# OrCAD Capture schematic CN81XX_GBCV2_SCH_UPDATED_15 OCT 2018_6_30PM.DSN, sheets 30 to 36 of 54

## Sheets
30 34.V0P9_DLM & V1P2_DDR: size B; title: V0P9_DLM&V1P2_DDR
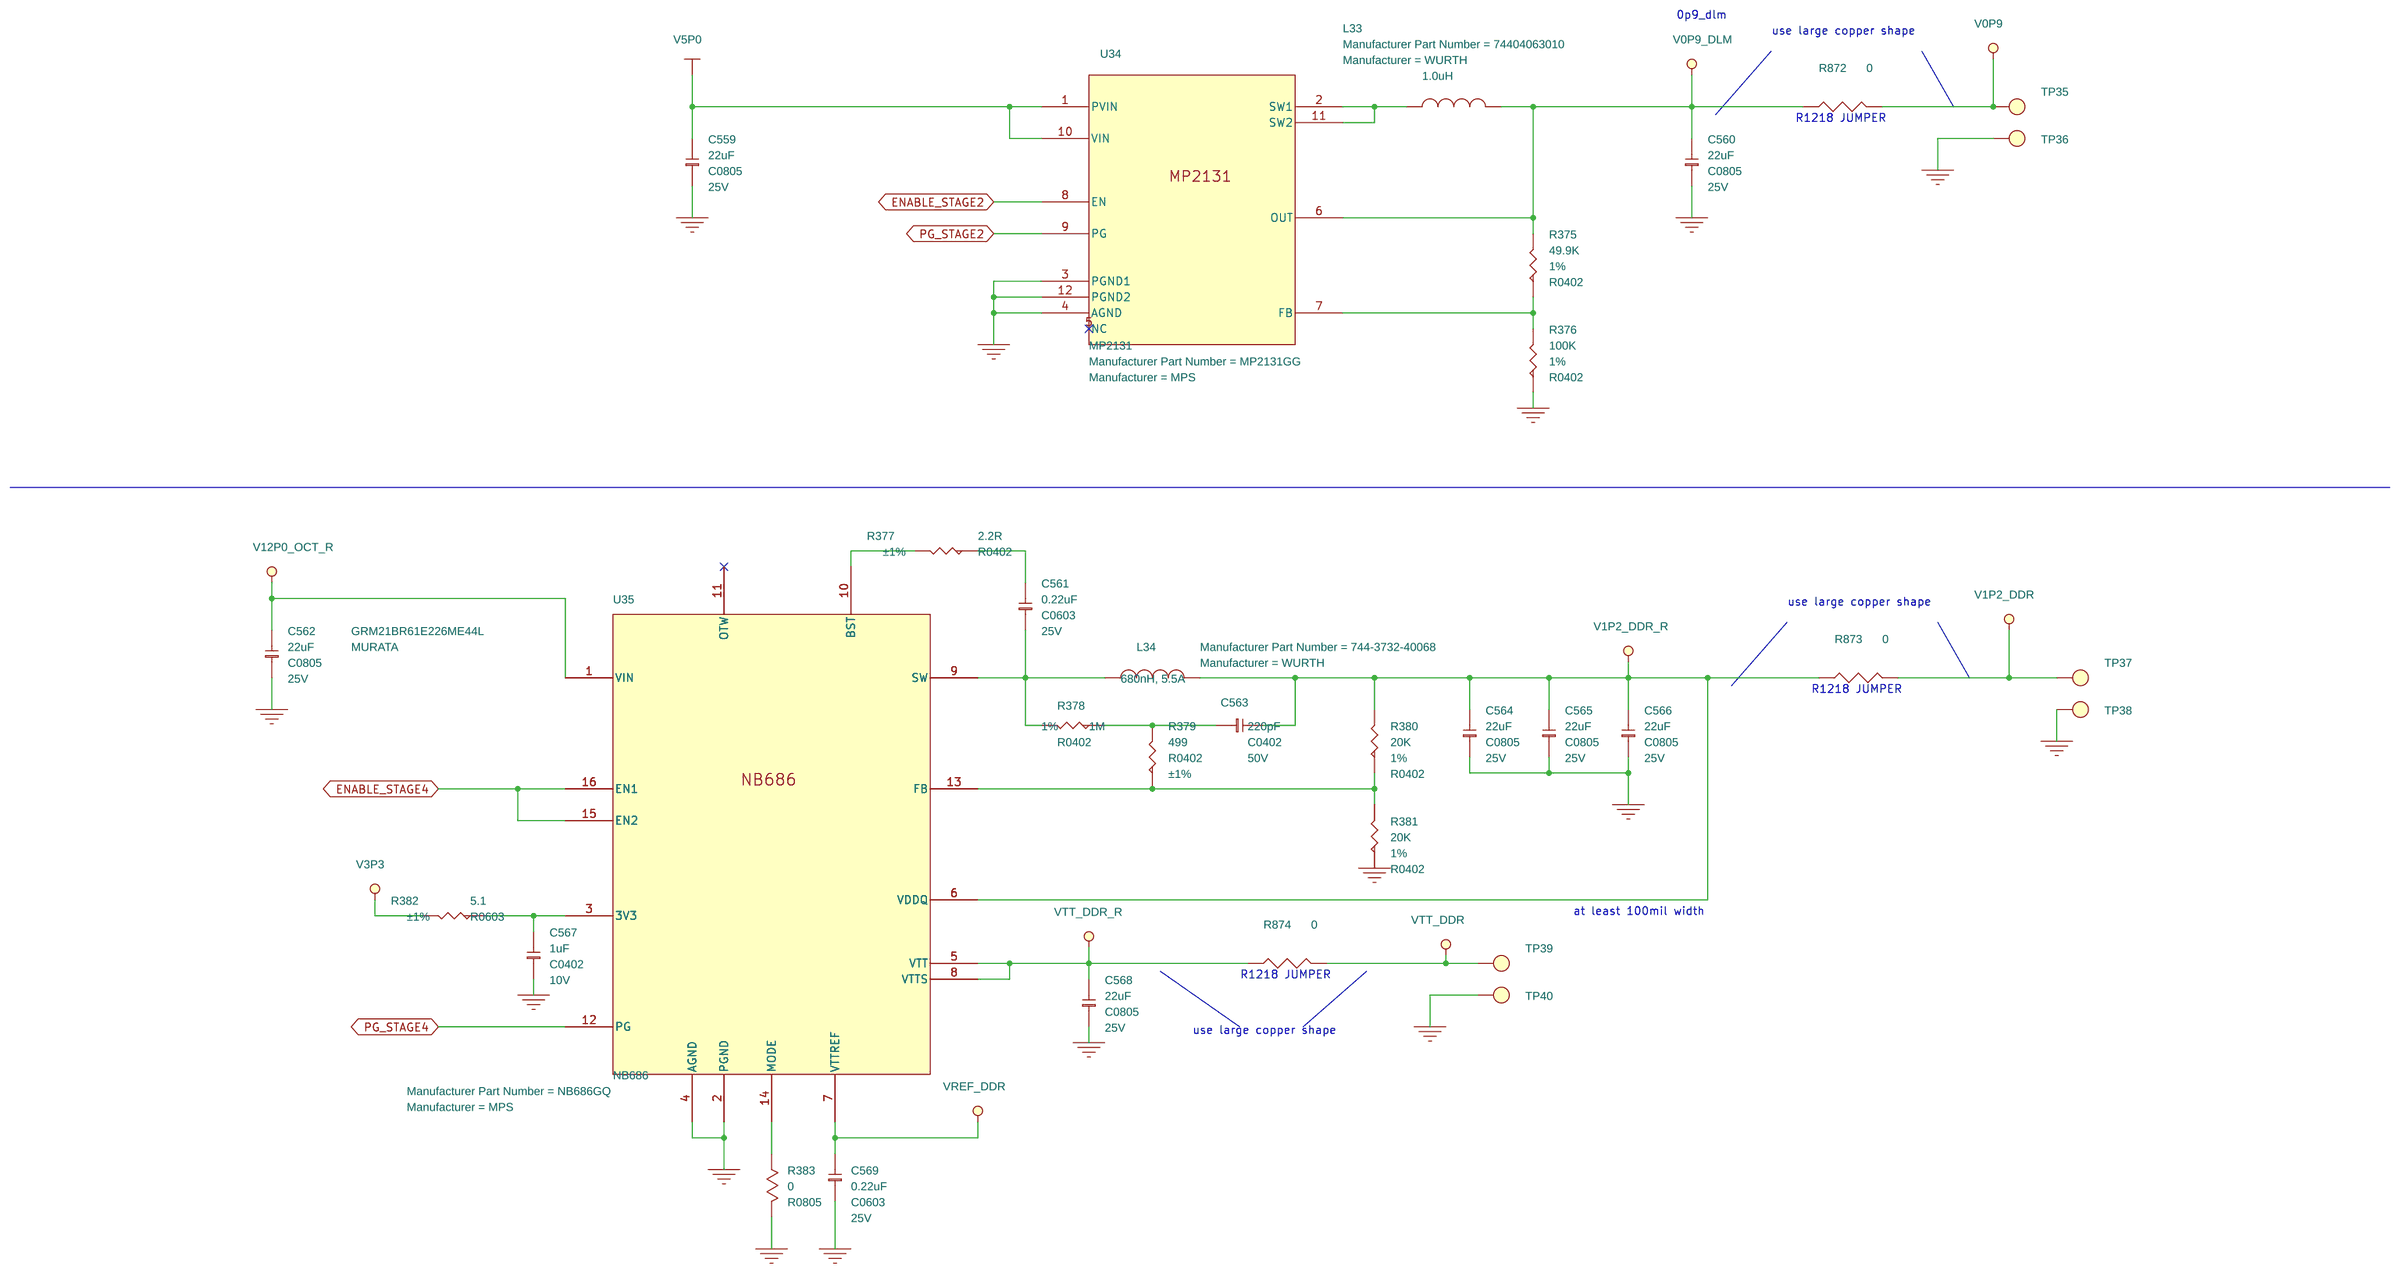
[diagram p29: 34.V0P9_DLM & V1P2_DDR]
31 35.TRXFE_PWR,V2P5,V0P9_ PLL: size B; title: V1P2,V2P5,V0P9_PLL
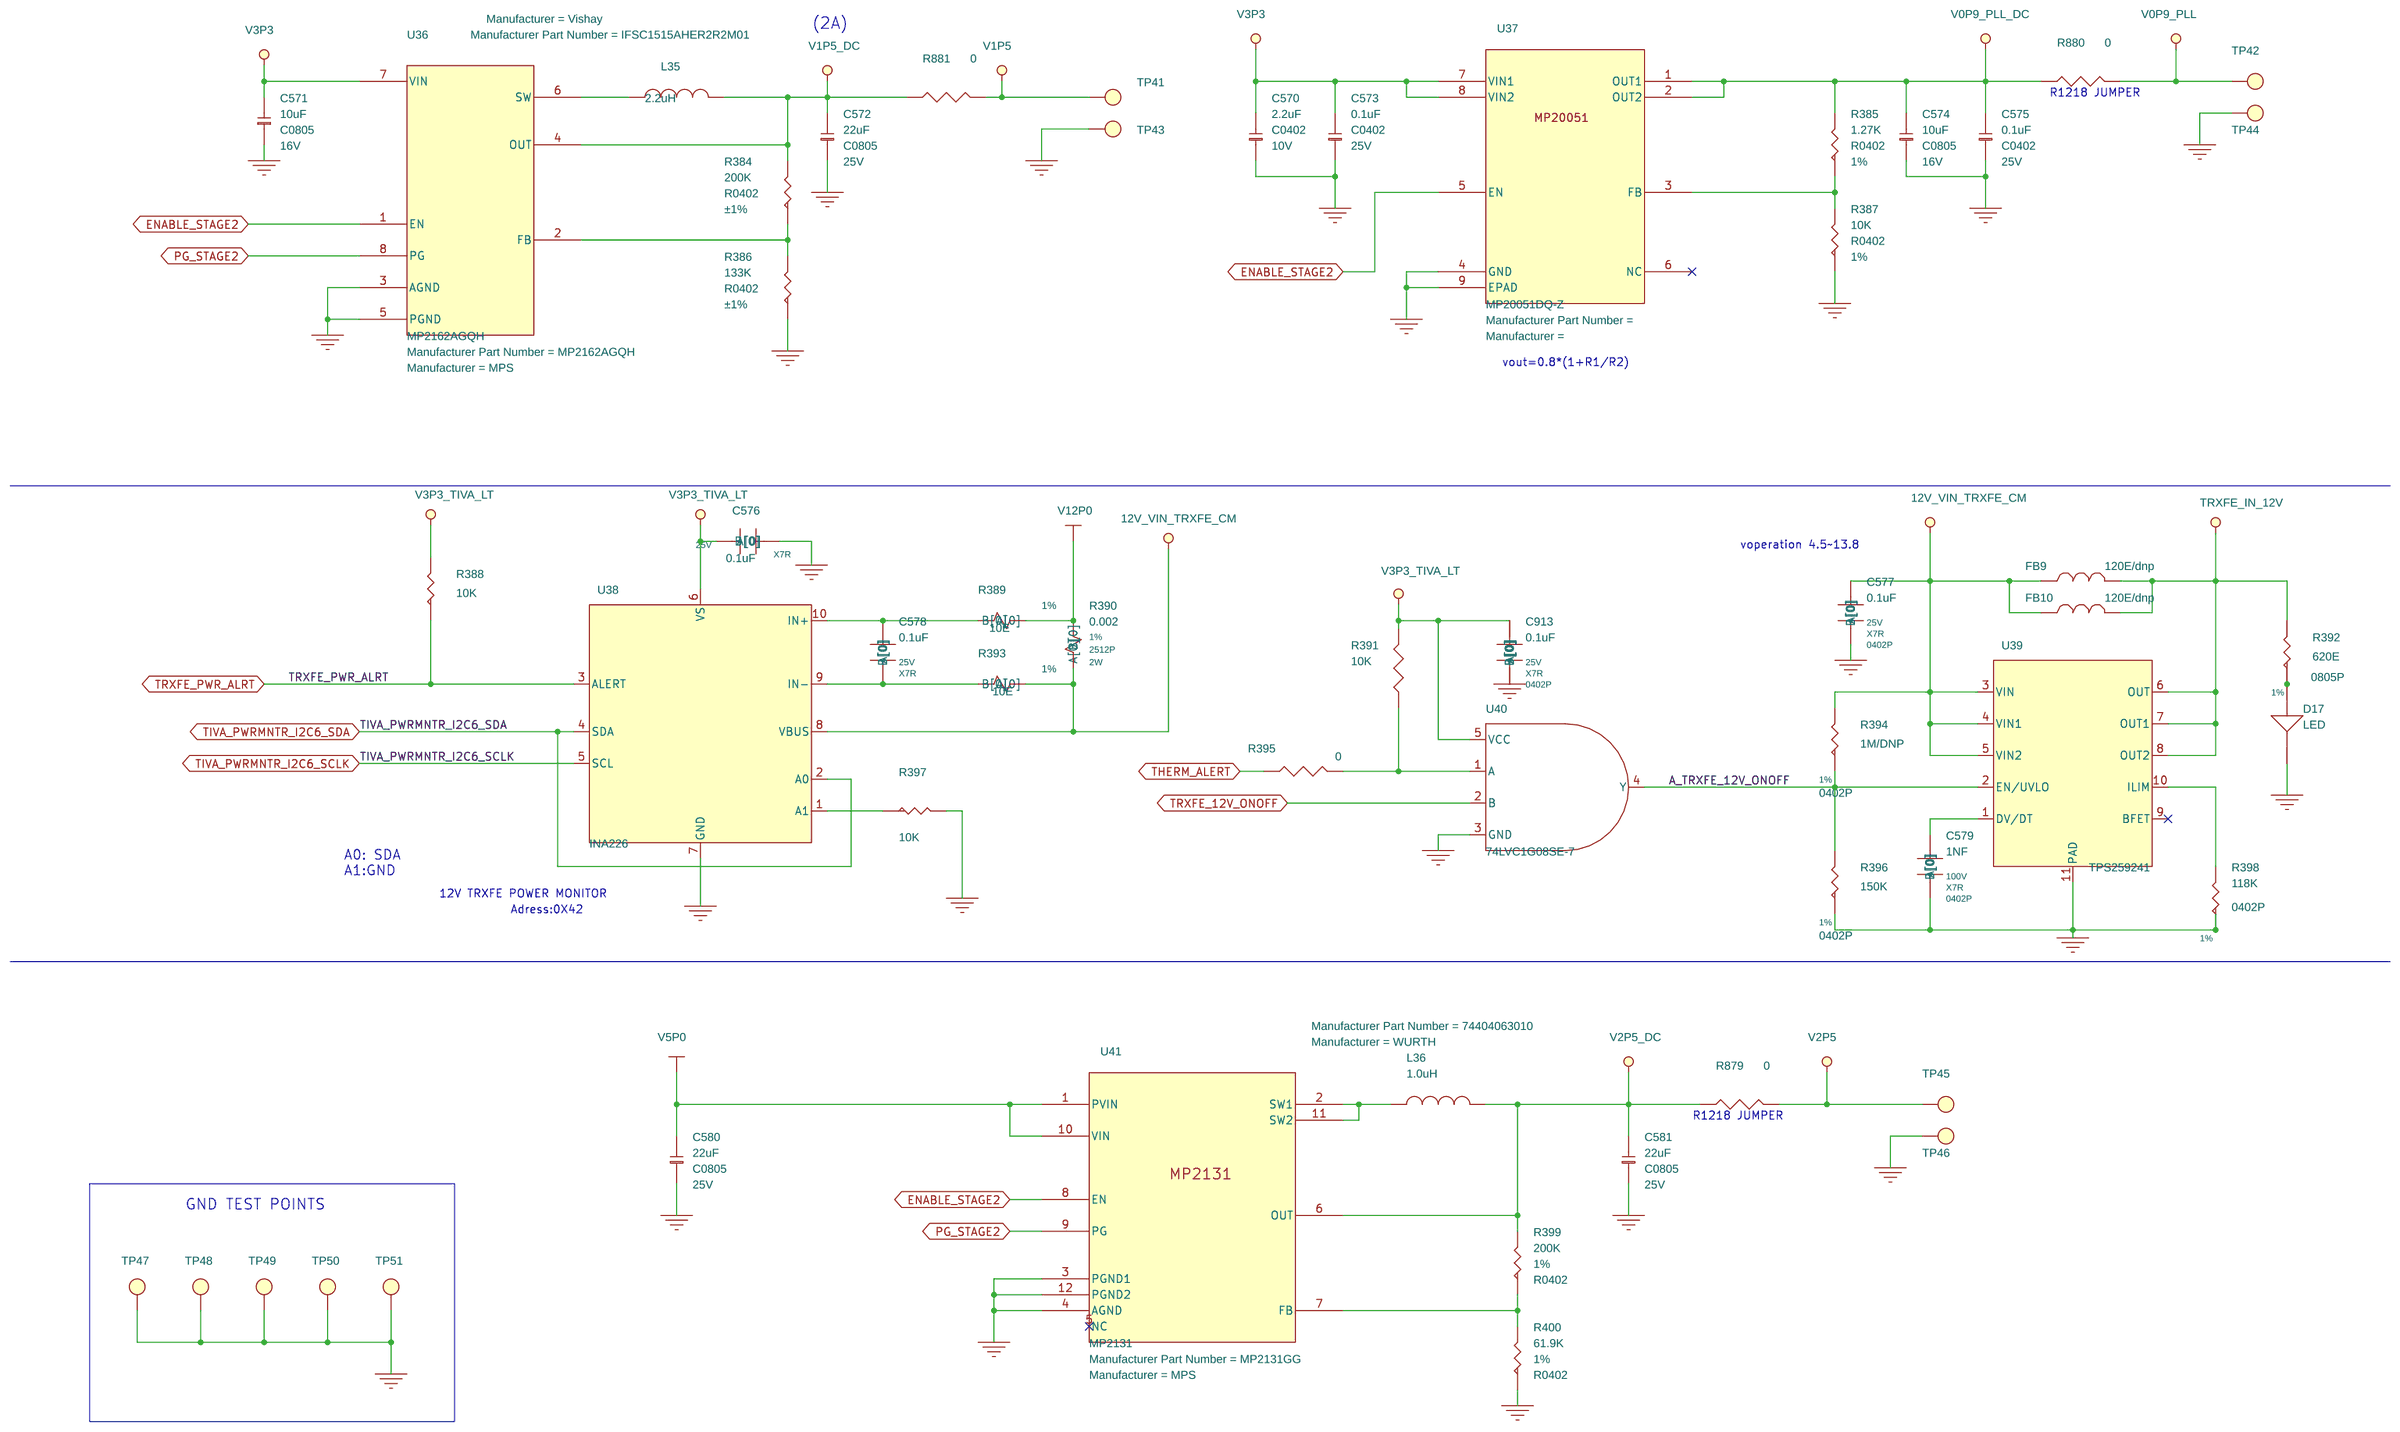
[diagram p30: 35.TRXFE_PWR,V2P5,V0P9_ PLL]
32 36.POWER AND RESET SEQUENCING: size B; title: POWER AND RESET
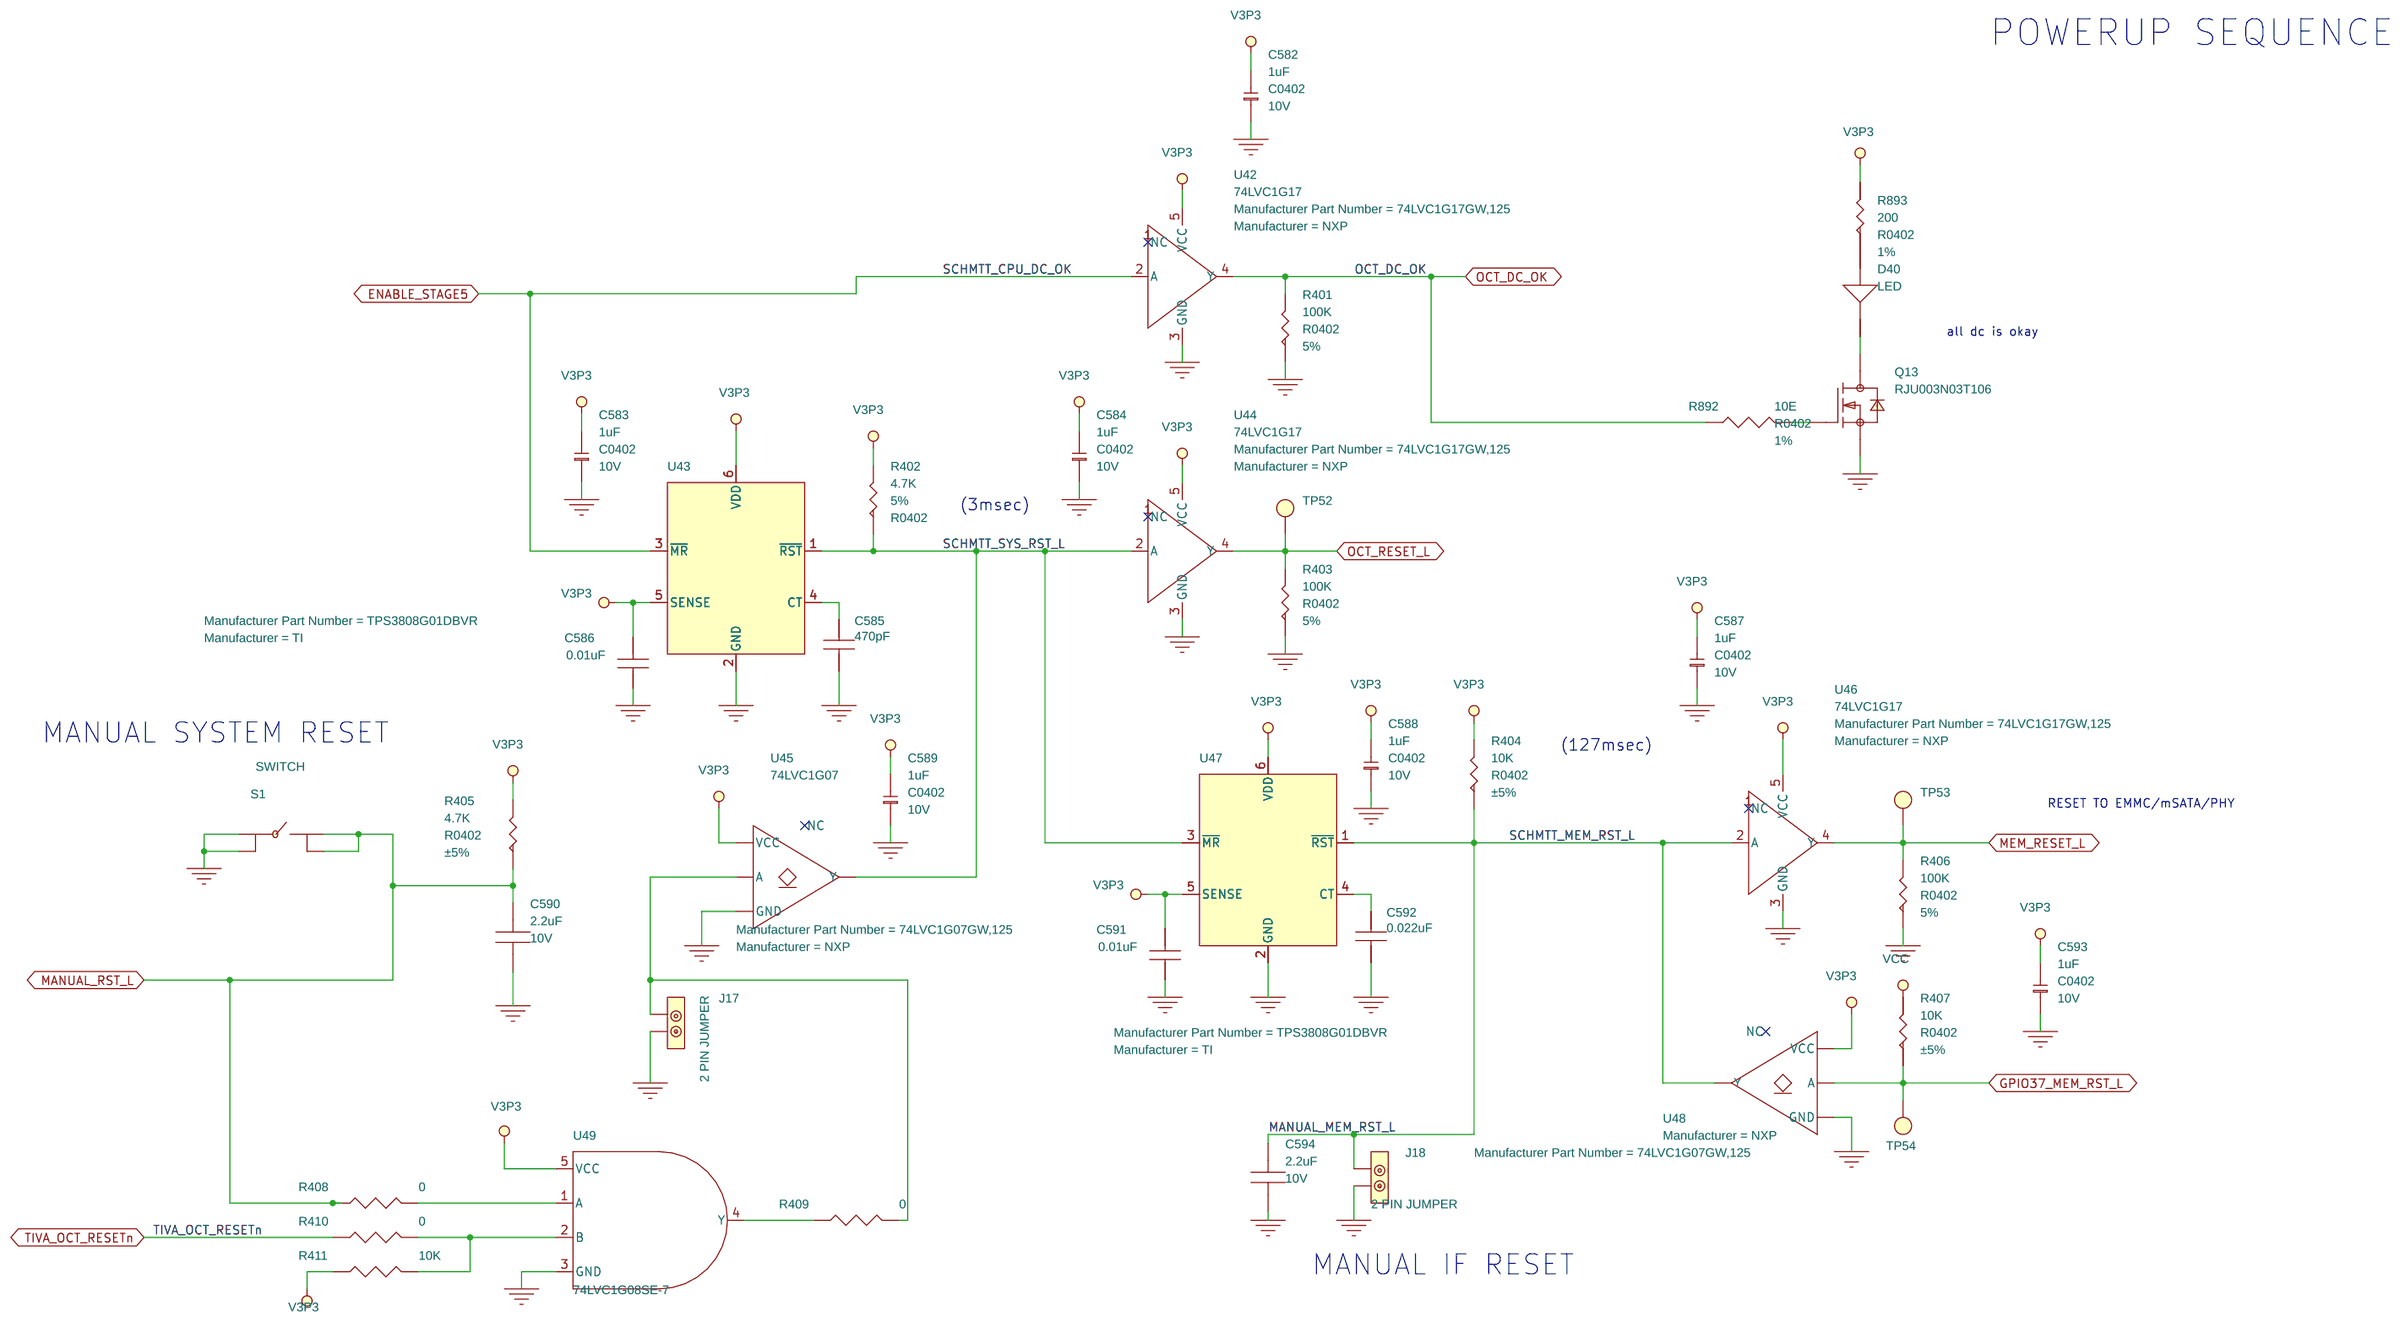
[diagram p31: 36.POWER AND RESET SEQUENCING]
33 37.POWER UP SEQUENCE: size B; title: POWER UP SEQUENCE
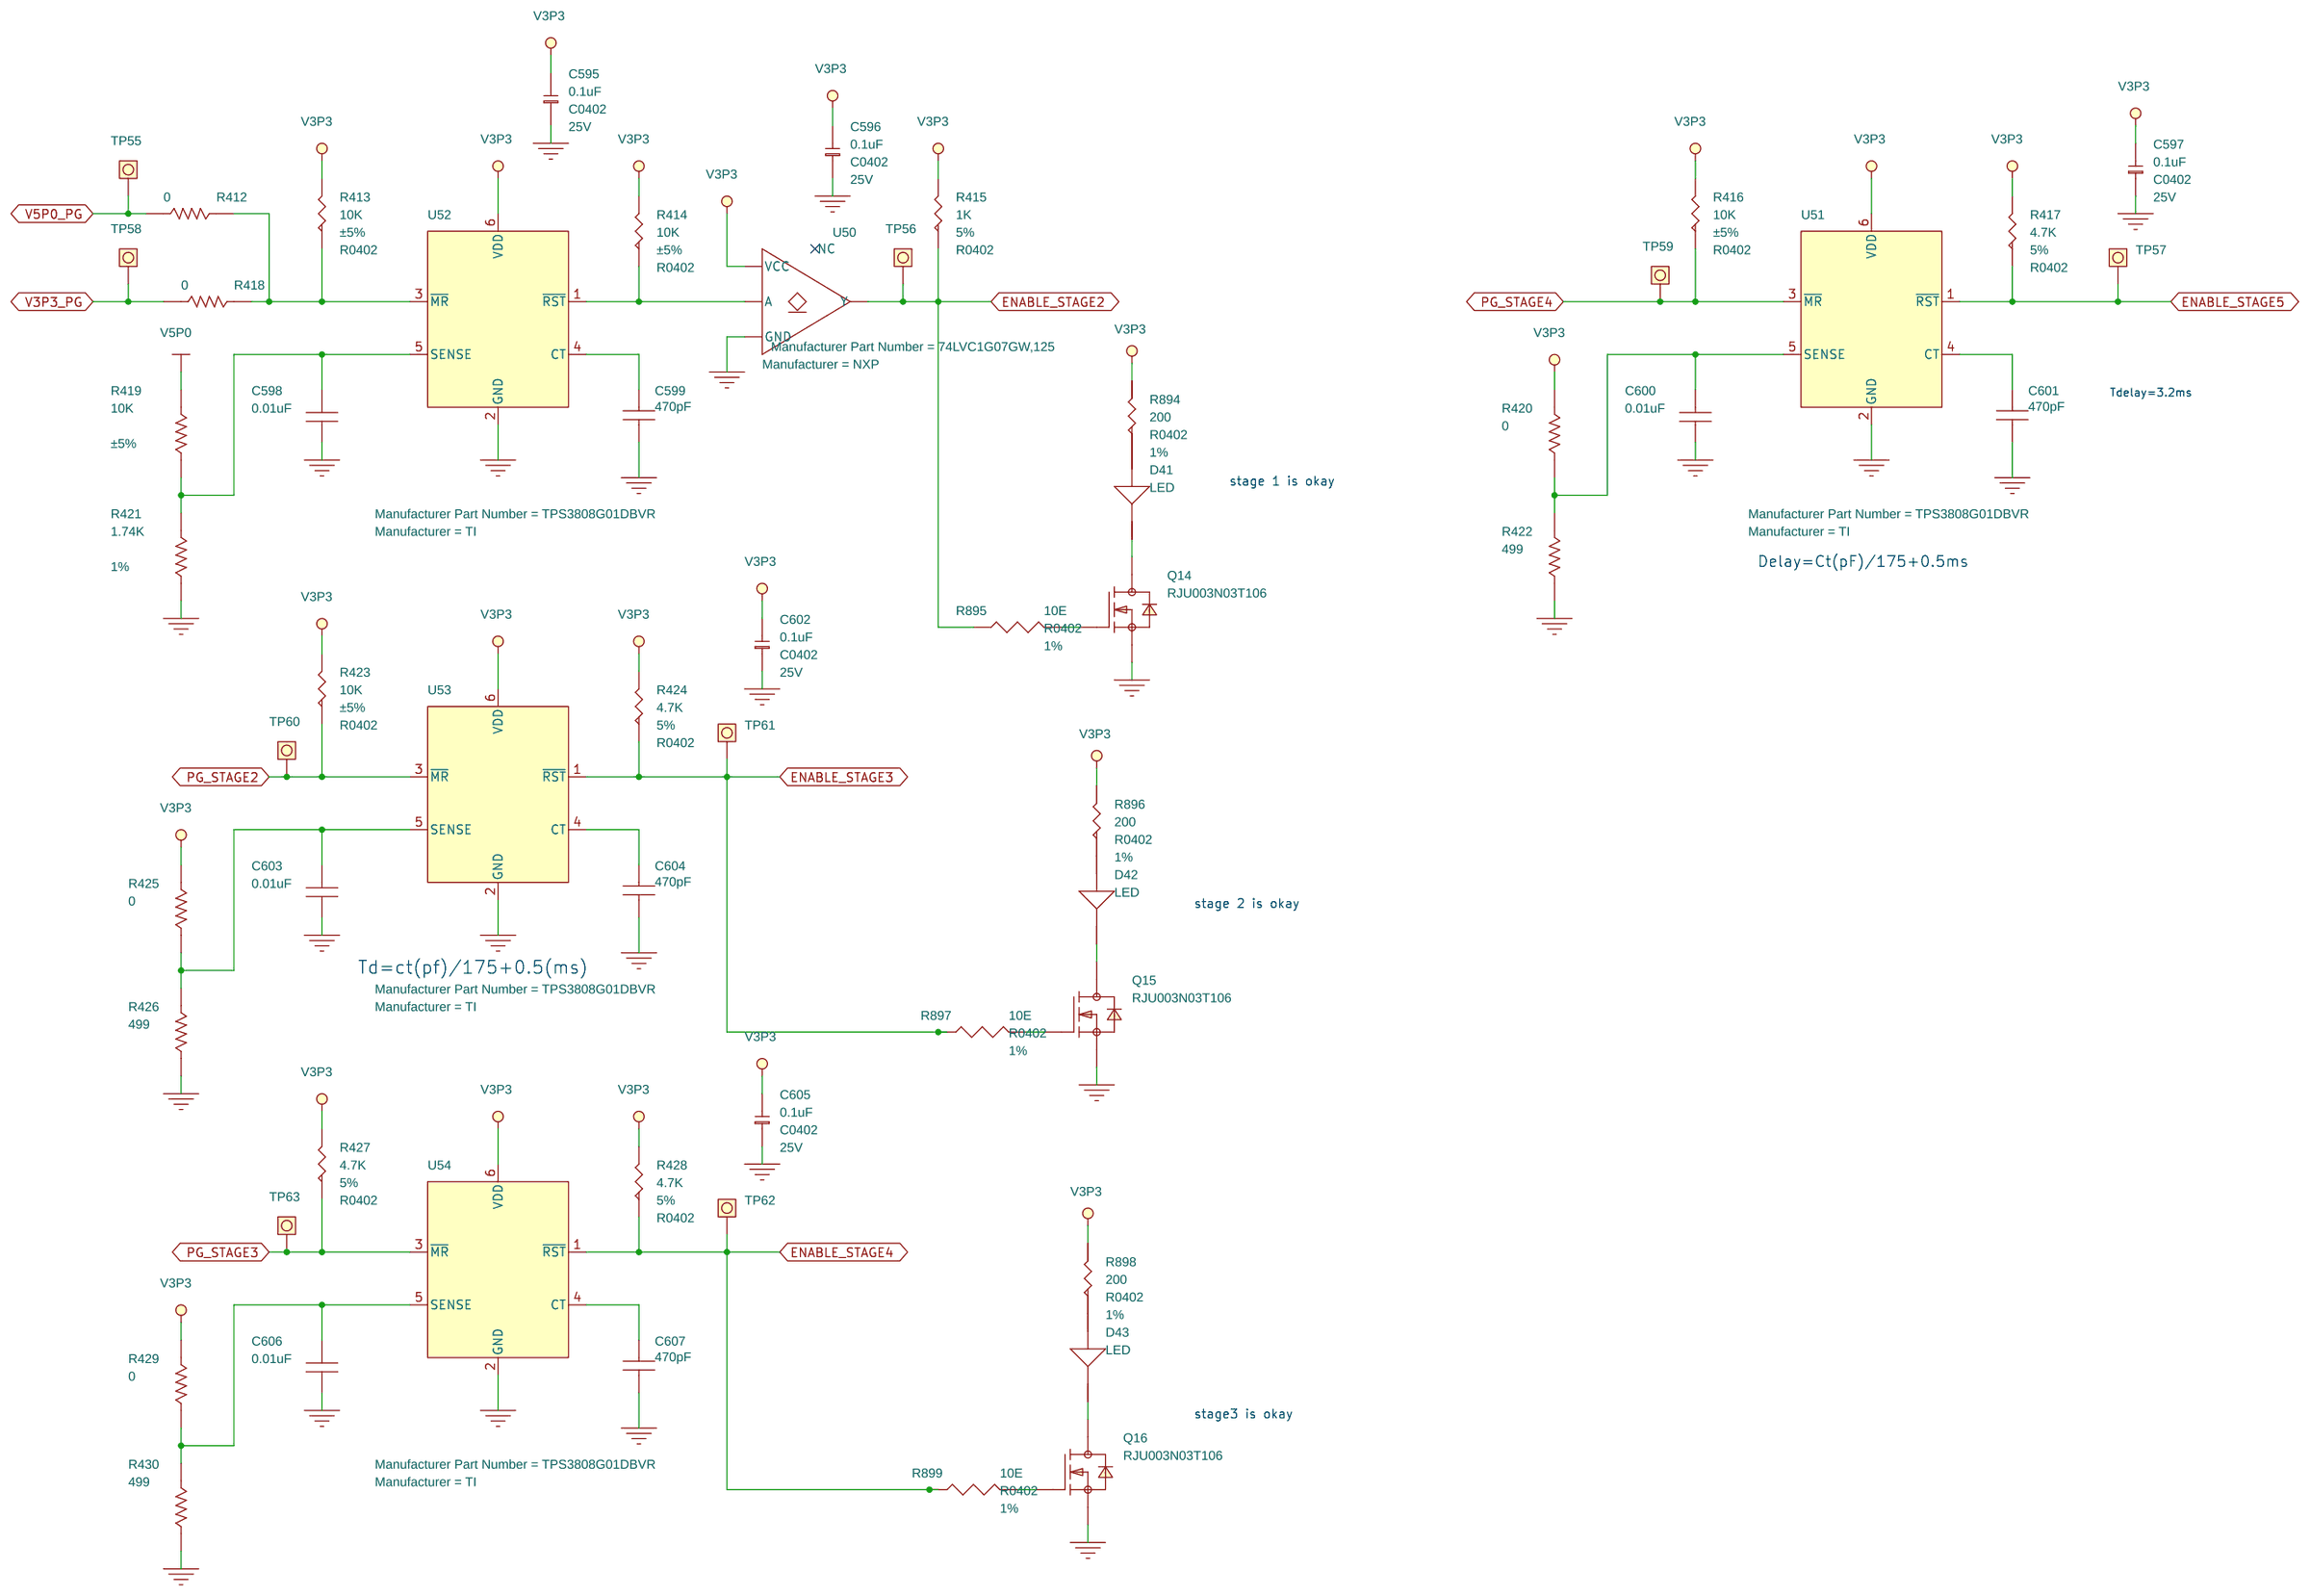
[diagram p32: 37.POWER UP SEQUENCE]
34 38. CLOCK DISTRIBUTIONS-1: size B; title: CLOCK DISTRIBUTIONS; company: Cavium Networks; note: 805 E. Middlefield Road; note: Mountain View, CA  94043
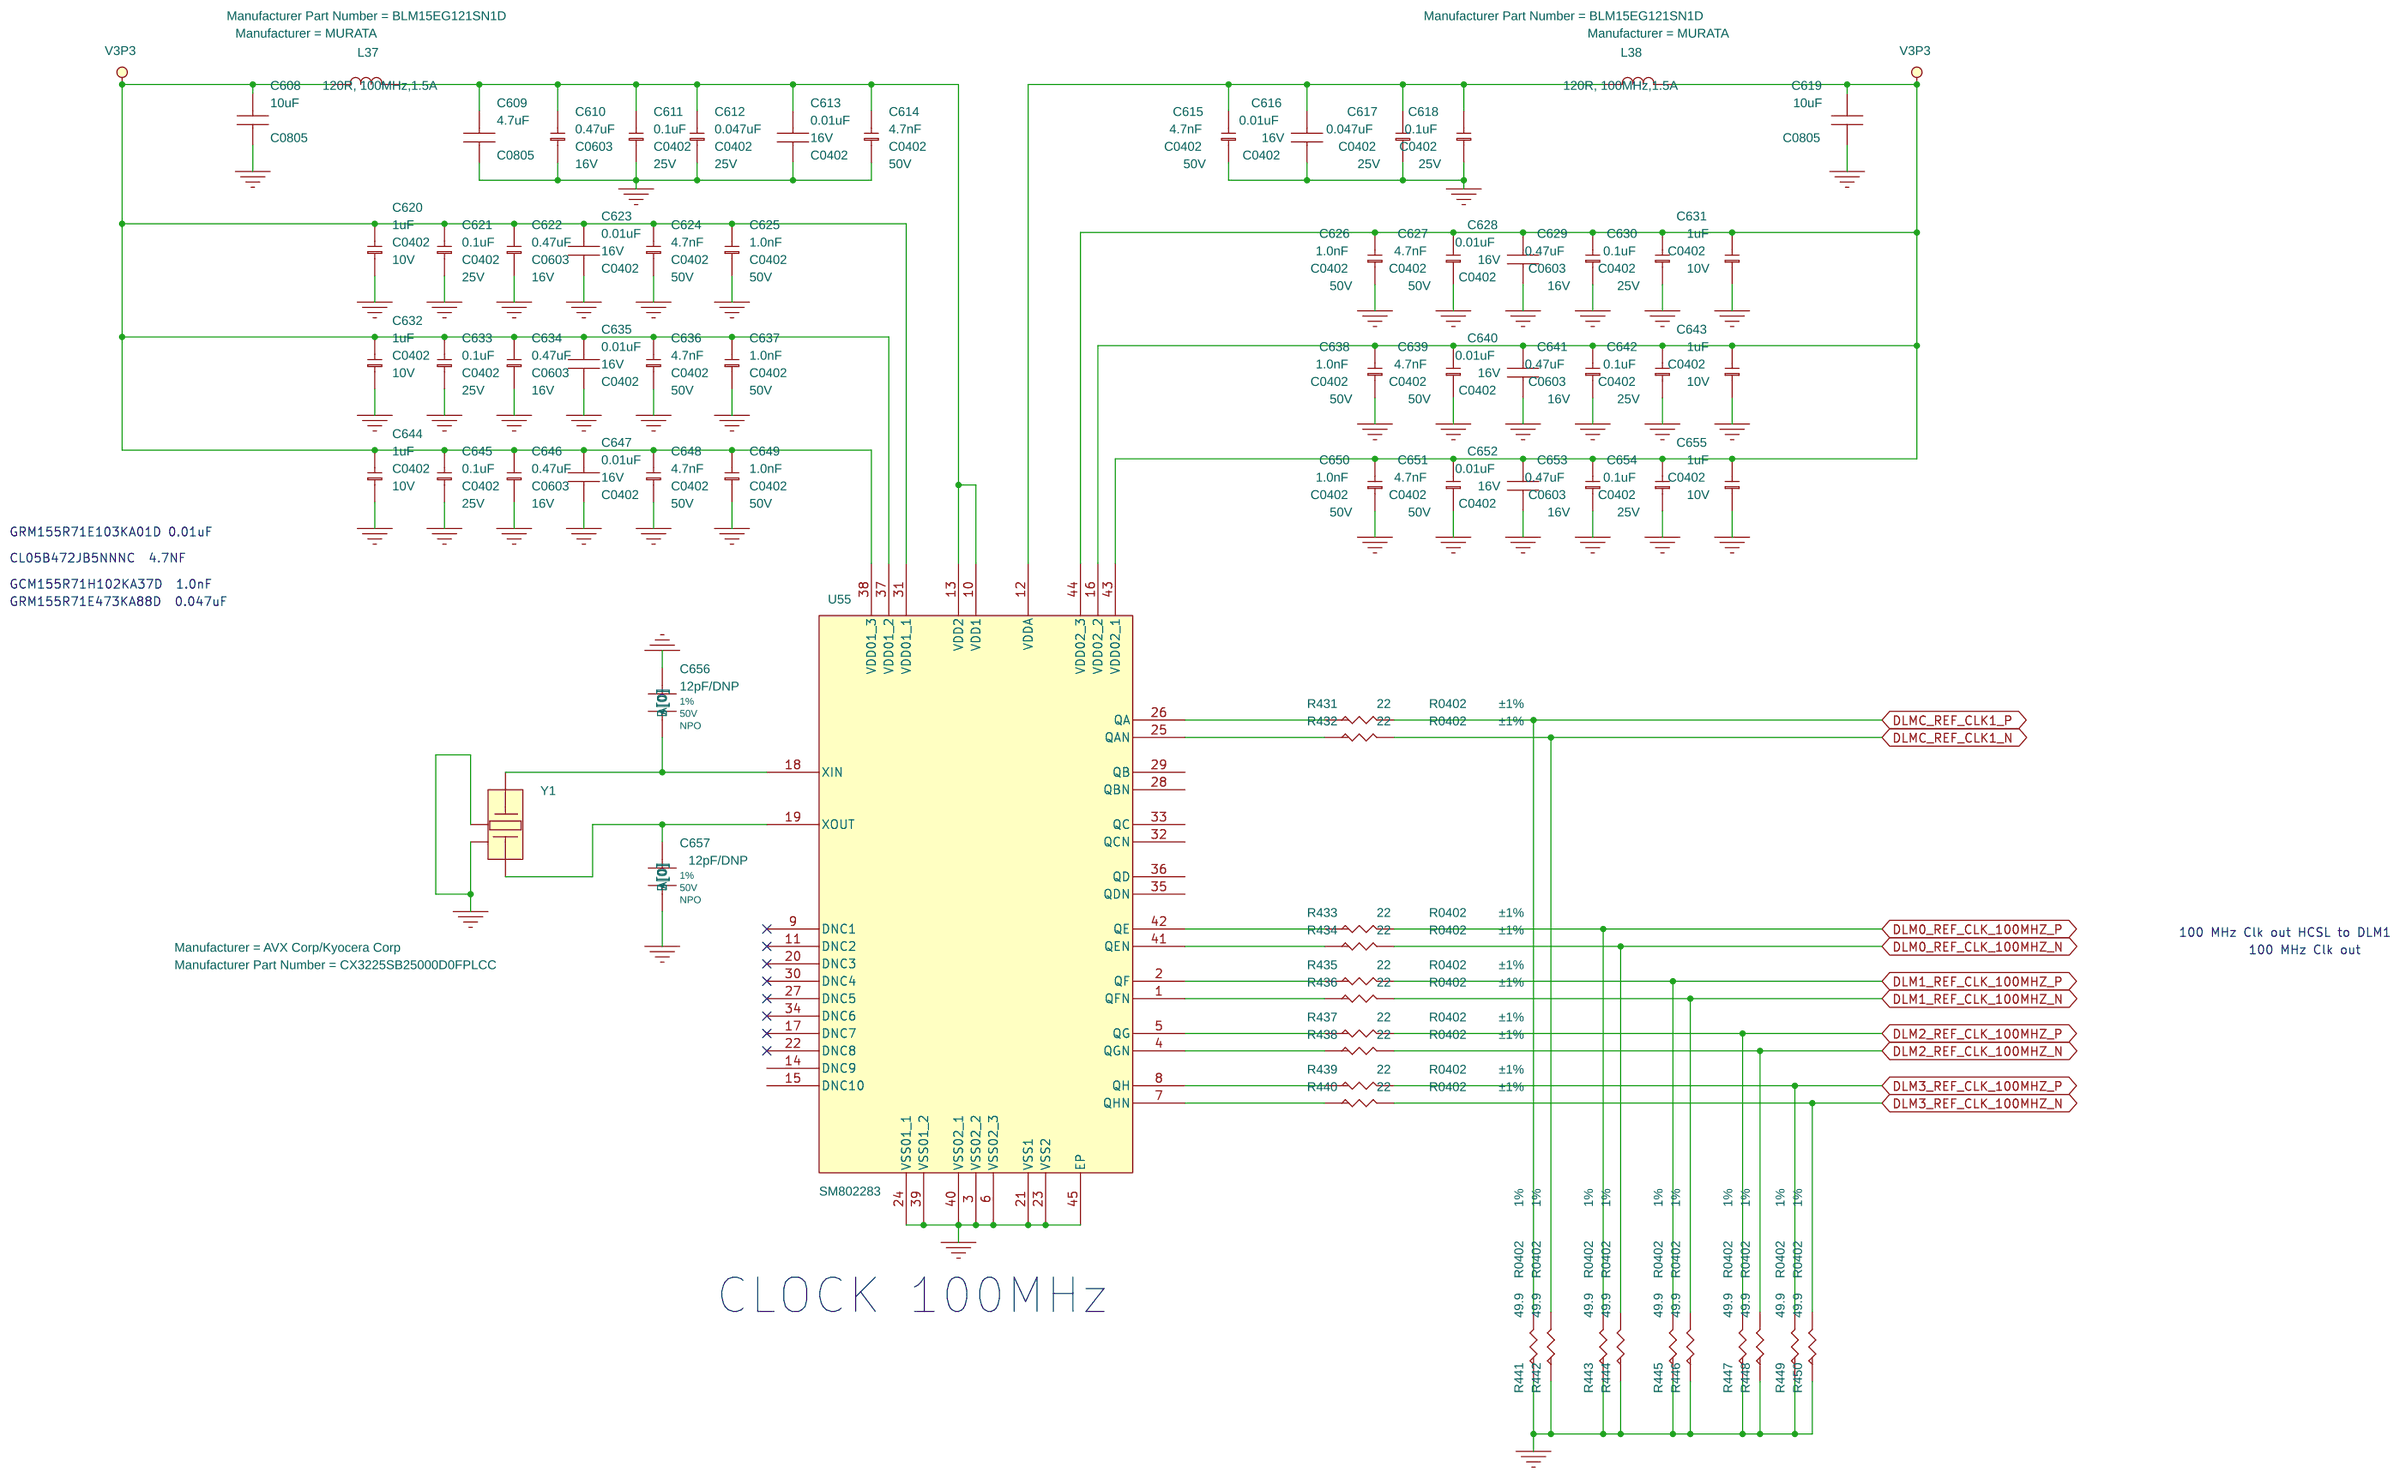
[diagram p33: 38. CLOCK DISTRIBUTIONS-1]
35 39. CLOCK DISTRIBUTIONS-2: size B; title: CLOCK DISTRIBUTIONS; company: Cavium Networks; note: 805 E. Middlefield Road; note: Mountain View, CA  94043
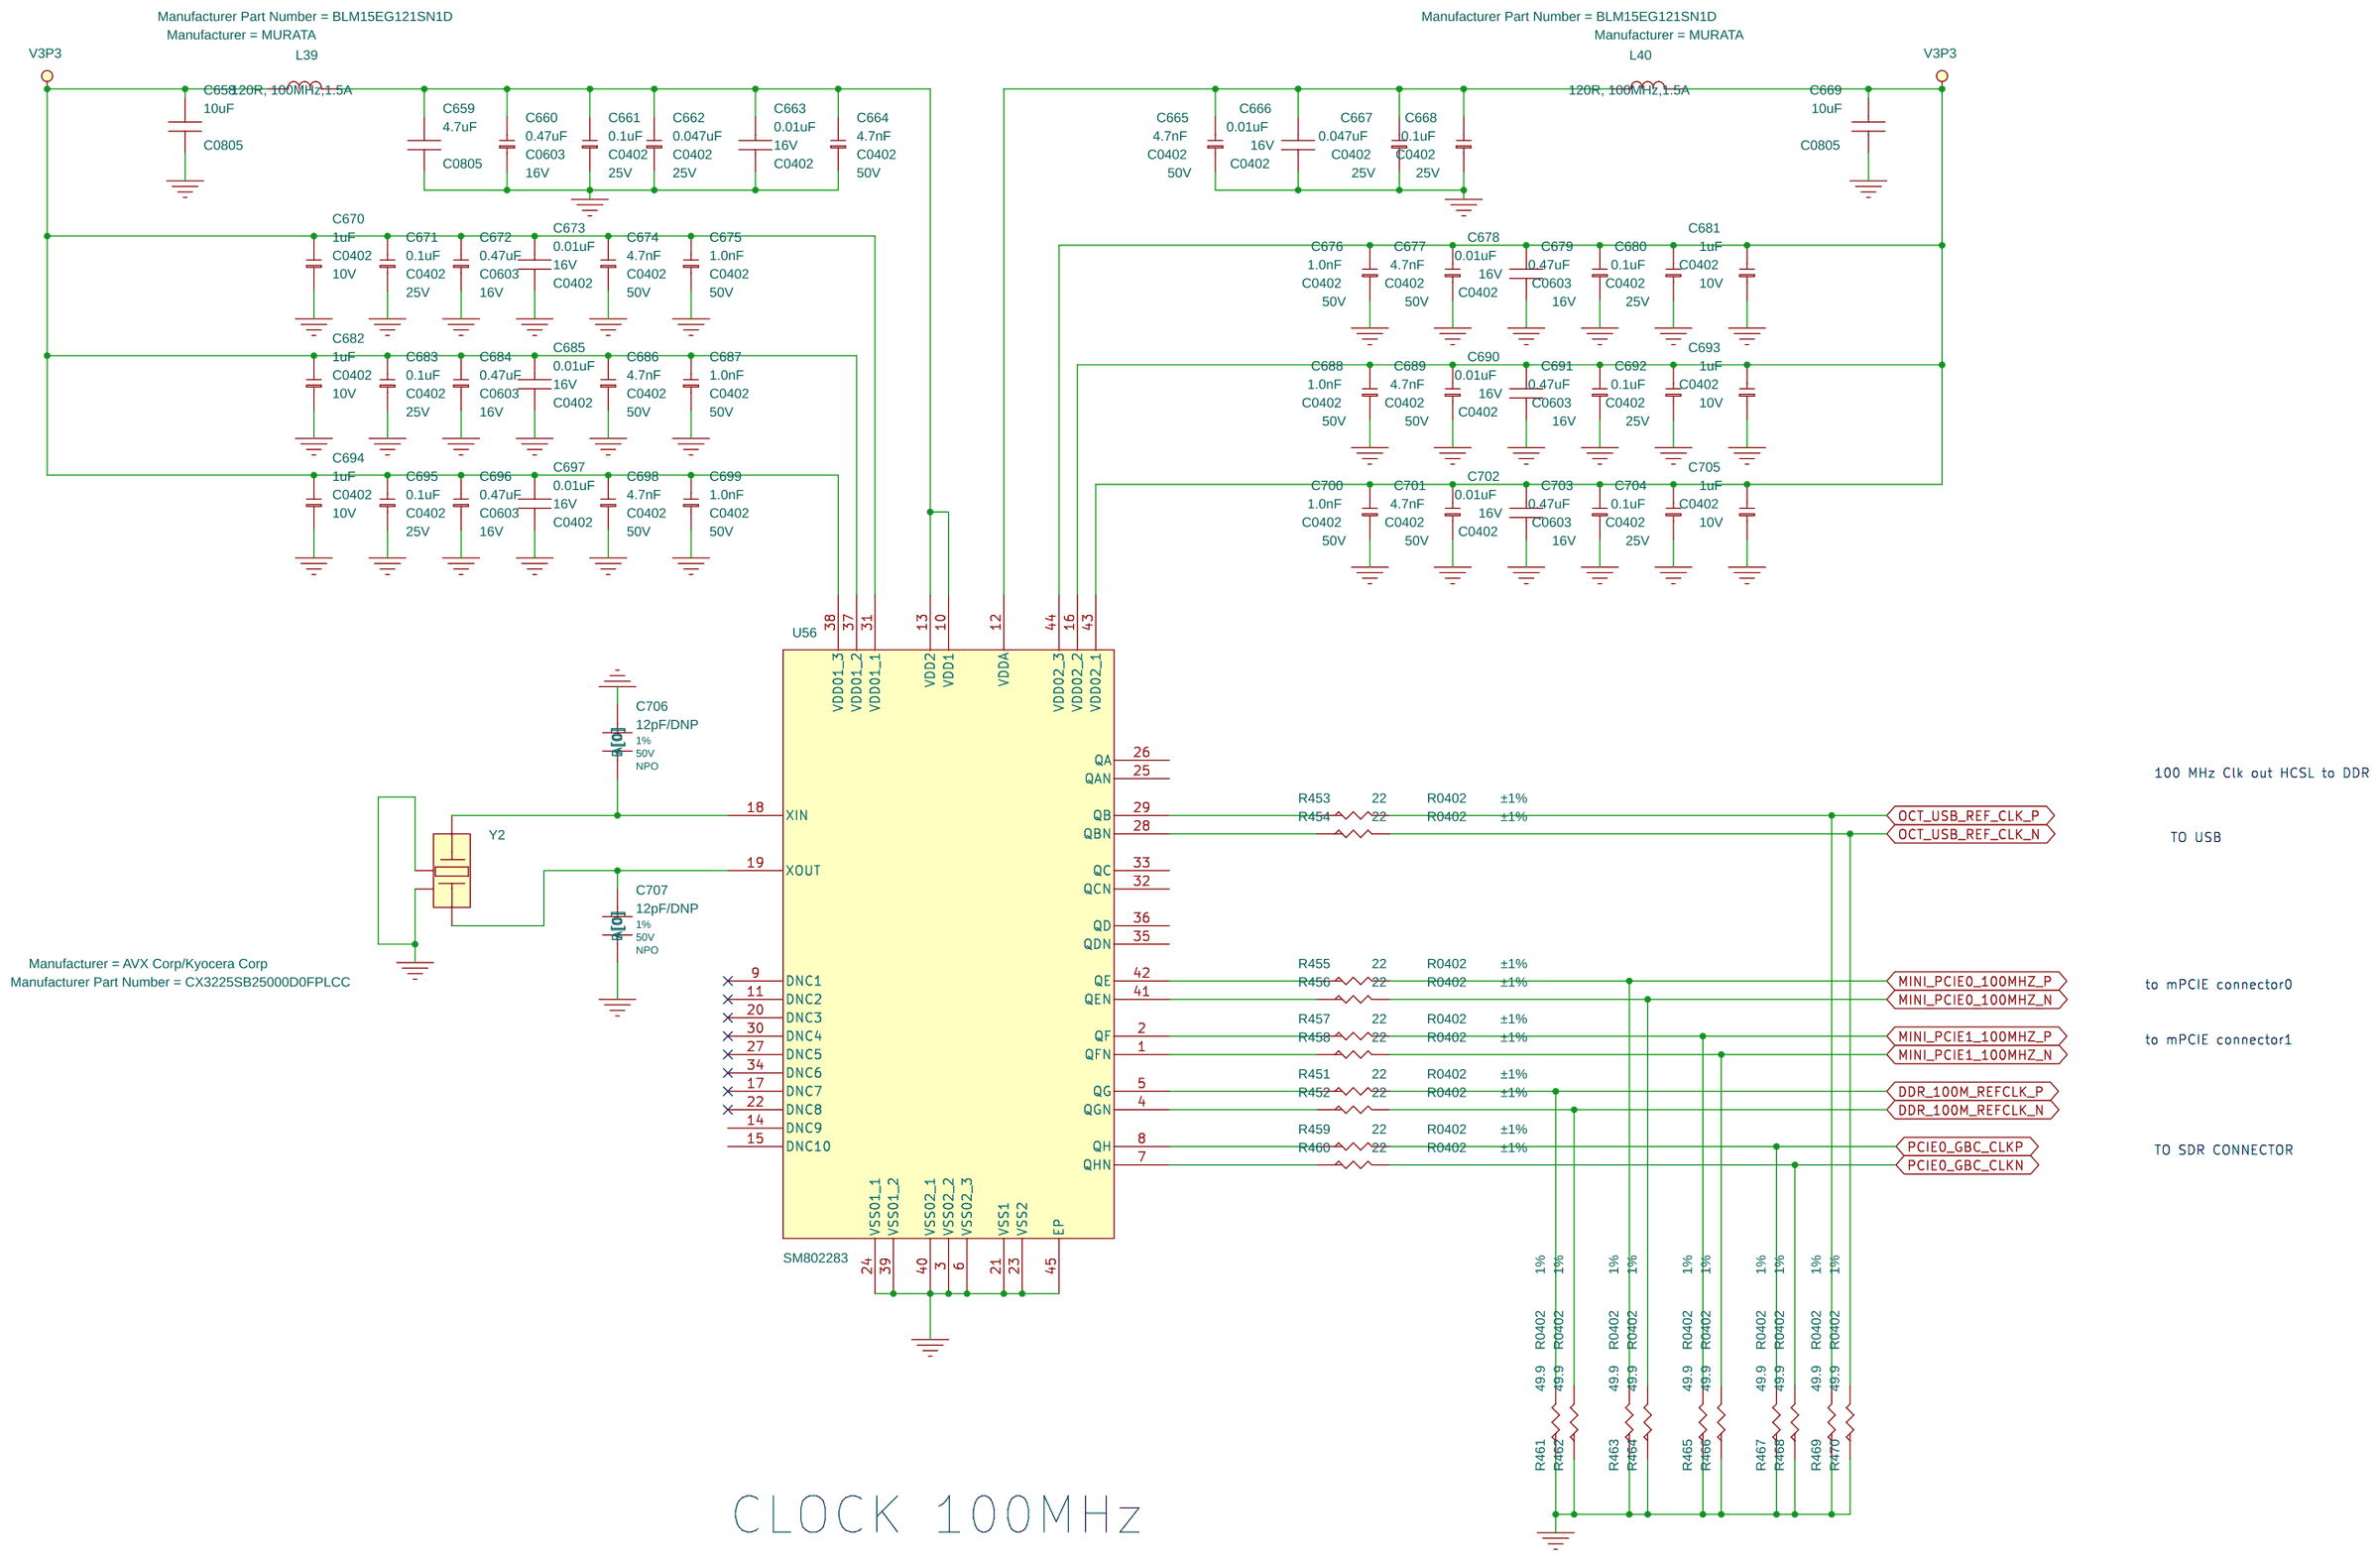
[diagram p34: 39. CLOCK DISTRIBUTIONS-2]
36 40.TIVA ETHERNET: size Custom; title: TIVA ETHERNET
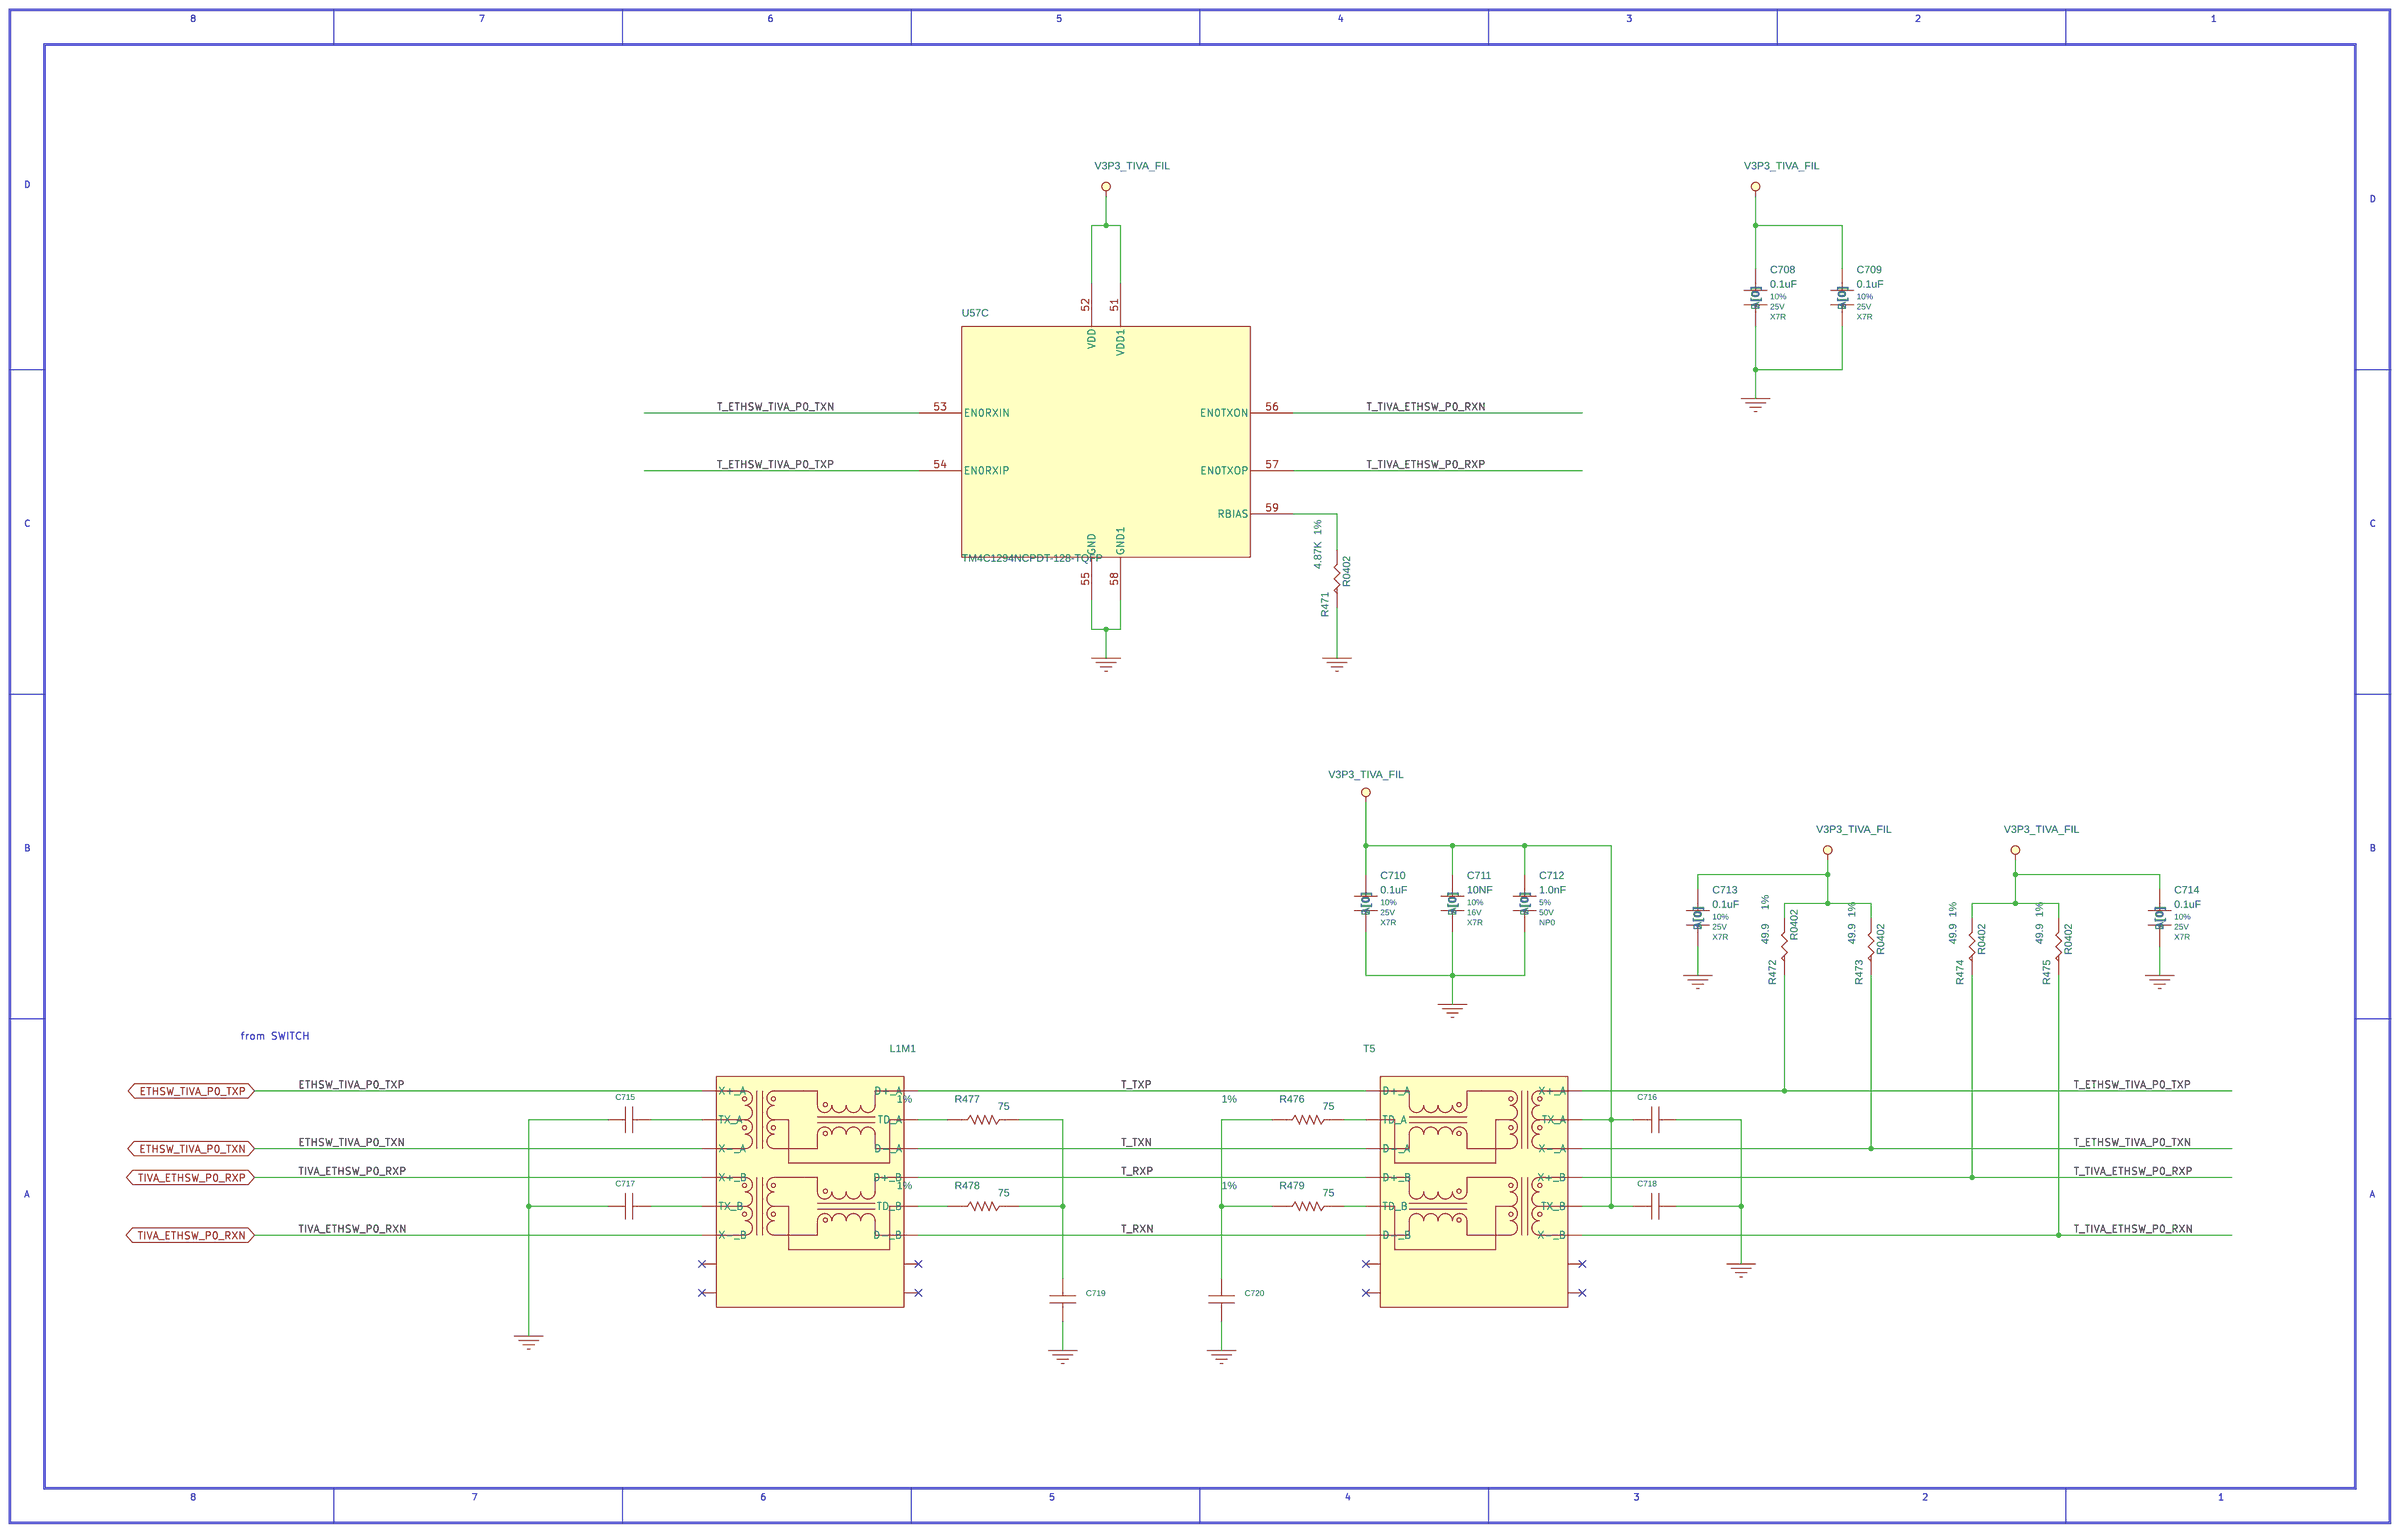
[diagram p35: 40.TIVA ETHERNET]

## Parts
sheet 34.V0P9_DLM & V1P2_DDR
C559  22uF  [C0805]
C560  22uF  [C0805]
C561  0.22uF  [C0603]
C562  22uF  [C0805]
C563  220pF  [C0402]
C564  22uF  [C0805]
C565  22uF  [C0805]
C566  22uF  [C0805]
C567  1uF  [C0402]
C568  22uF  [C0805]
C569  0.22uF  [C0603]
L33  1.0uH  [IND6060X280]
L34  680nH, 5.5A  [SMT_4P45MMX4P06MMX2MM]
R375  49.9K  [R0402]
R376  100K  [R0402]
R377  2.2R  [R0402]
R378  1M  [R0402]
R379  499  [R0402]
R380  20K  [R0402]
R381  20K  [R0402]
R382  5.1  [R0603]
R383  0  [R0805]
R872  0  [R1812]
R873  0  [R1812]
R874  0  [R1812]
TP35  TP_PWR  [TP_TH_40MIL]
TP36  TP_PWR  [TP_TH_40MIL]
TP37  TP_PWR  [TP_TH_40MIL]
TP38  TP_PWR  [TP_TH_40MIL]
TP39  TP_PWR  [TP_TH_40MIL]
TP40  TP_PWR  [TP_TH_40MIL]
U34  MP2131  [QFN12_MP2131]
U35  NB686  [QFN16_NB686]
sheet 35.TRXFE_PWR,V2P5,V0P9_ PLL
C570  2.2uF  [C0402]
C571  10uF  [C0805]
C572  22uF  [C0805]
C573  0.1uF  [C0402]
C574  10uF  [C0805]
C575  0.1uF  [C0402]
C576  0.1uF  [C0402]
C577  0.1uF  [C0402]
C578  0.1uF  [C0402]
C579  1NF  [C0402]
C580  22uF  [C0805]
C581  22uF  [C0805]
C913  0.1uF  [C0402]
D17  LED  [LED_LTST-C190]
FB9  120E/dnp  [INDC1608X95M]
FB10  120E/dnp  [INDC1608X95M]
L35  2.2uH  [IND3838X190]
L36  1.0uH  [IND6060X280]
R384  200K  [R0402]
R385  1.27K  [R0402]
R386  133K  [R0402]
R387  10K  [R0402]
R388  10K  [R0402]
R389  10E  [R0402]
R390  0.002  [R2512]
R391  10K  [R0402]
R392  620E  [R0805]
R393  10E  [R0402]
R394  1M/DNP  [R0402]
R395  0  [R0402]
R396  150K  [R0402]
R397  10K  [R0402]
R398  118K  [R0402]
R399  200K  [R0402]
R400  61.9K  [R0402]
R879  0  [R1812]
R880  0  [R1812]
R881  0  [R1812]
TP41  TP_PWR  [TP_TH_40MIL]
TP42  TP_PWR  [TP_TH_40MIL]
TP43  TP_PWR  [TP_TH_40MIL]
TP44  TP_PWR  [TP_TH_40MIL]
TP45  TP_PWR  [TP_TH_40MIL]
TP46  TP_PWR  [TP_TH_40MIL]
TP47  TP_PWR  [TP_TH_40MIL]
TP48  TP_PWR  [TP_TH_40MIL]
TP49  TP_PWR  [TP_TH_40MIL]
TP50  TP_PWR  [TP_TH_40MIL]
TP51  TP_PWR  [TP_TH_40MIL]
U36  MP2162AGQH  [QFN8]
U37  MP20051DQ-Z  [QFN8_MP20051]
U38  INA226  [VSSOP50P490X110-10N]
U39  TPS259241  [TPS259241]
U40  74LVC1G08SE-7  [SC70_5P]
U41  MP2131  [QFN12_MP2131]
sheet 36.POWER AND RESET SEQUENCING
C582  1uF  [C0402]
C583  1uF  [C0402]
C584  1uF  [C0402]
C585  470pF  [C0402]
C586  0.01uF  [C0402]
C587  1uF  [C0402]
C588  1uF  [C0402]
C589  1uF  [C0402]
C590  2.2uF  [C0402]
C591  0.01uF  [C0402]
C592  0.022uF  [C0402]
C593  1uF  [C0402]
C594  2.2uF  [C0402]
D40  LED  [LED_LTST-C190]
J17  2 PIN JUMPER  [TH_PITCH2P54MMXLENGTH5P84MM]
J18  2 PIN JUMPER  [TH_PITCH2P54MMXLENGTH5P84MM]
Q13  RJU003N03  [UMT3]
R401  100K  [R0402]
R402  4.7K  [R0402]
R403  100K  [R0402]
R404  10K  [R0402]
R405  4.7K  [R0402]
R406  100K  [R0402]
R407  10K  [R0402]
R408  0  [R0402]
R409  0  [R0402]
R410  0  [R0402]
R411  10K  [EIA-0402]
R892  10E  [R0402]
R893  200  [R0402]
S1  SWITCH  [SW_B3SL-1022P]
TP52  TP_PWR  [TP_TH_40MIL]
TP53  TP_PWR  [TP_TH_40MIL]
TP54  TP_PWR  [TP_TH_40MIL]
U42  74LVC1G17  [TSSOP5]
U43  TPS3808G01DBVR  [6SOT23_TPS3808]
U44  74LVC1G17  [TSSOP5]
U45  74LVC1G07  [5-TSSOP]
U46  74LVC1G17  [TSSOP5]
U47  TPS3808G01DBVR  [6SOT23_TPS3808]
U48  74LVC1G07  [5-TSSOP]
U49  74LVC1G08SE-7  [SC70_5P]
sheet 37.POWER UP SEQUENCE
C595  0.1uF  [C0402]
C596  0.1uF  [C0402]
C597  0.1uF  [C0402]
C598  0.01uF  [C0402]
C599  470pF  [C0402]
C600  0.01uF  [C0402]
C601  470pF  [C0402]
C602  0.1uF  [C0402]
C603  0.01uF  [C0402]
C604  470pF  [C0402]
C605  0.1uF  [C0402]
C606  0.01uF  [C0402]
C607  470pF  [C0402]
D41  LED  [LED_LTST-C190]
D42  LED  [LED_LTST-C190]
D43  LED  [LED_LTST-C190]
Q14  RJU003N03  [UMT3]
Q15  RJU003N03  [UMT3]
Q16  RJU003N03  [UMT3]
R412  0  [R0402]
R413  10K  [R0402]
R414  10K  [R0402]
R415  1K  [R0402]
R416  10K  [R0402]
R417  4.7K  [R0402]
R418  0  [R0402]
R419  10K  [R0402]
R420  0  [R0402]
R421  1.74K  [R0402]
R422  499  [R0402]
R423  10K  [R0402]
R424  4.7K  [R0402]
R425  0  [R0402]
R426  499  [R0402]
R427  4.7K  [R0402]
R428  4.7K  [R0402]
R429  0  [R0402]
R430  499  [R0402]
R894  200  [R0402]
R895  10E  [R0402]
R896  200  [R0402]
R897  10E  [R0402]
R898  200  [R0402]
R899  10E  [R0402]
TP55  TEST POINT  [TP_SMD]
TP56  TEST POINT  [TP_SMD]
TP57  TEST POINT  [TP_SMD]
TP58  TEST POINT  [TP_SMD]
TP59  TEST POINT  [TP_SMD]
TP60  TEST POINT  [TP_SMD]
TP61  TEST POINT  [TP_SMD]
TP62  TEST POINT  [TP_SMD]
TP63  TEST POINT  [TP_SMD]
U50  74LVC1G07  [5-TSSOP]
U51  TPS3808G01DBVR  [6SOT23_TPS3808]
U52  TPS3808G01DBVR  [6SOT23_TPS3808]
U53  TPS3808G01DBVR  [6SOT23_TPS3808]
U54  TPS3808G01DBVR  [6SOT23_TPS3808]
sheet 38. CLOCK DISTRIBUTIONS-1
C608  10uF  [C0805]
C609  4.7uF  [C0805]
C610  0.47uF  [C0603]
C611  0.1uF  [C0402]
C612  0.047uF  [C0402]
C613  0.01uF  [C0402]
C614  4.7nF  [C0402]
C615  4.7nF  [C0402]
C616  0.01uF  [C0402]
C617  0.047uF  [C0402]
C618  0.1uF  [C0402]
C619  10uF  [C0805]
C620  1uF  [C0402]
C621  0.1uF  [C0402]
C622  0.47uF  [C0603]
C623  0.01uF  [C0402]
C624  4.7nF  [C0402]
C625  1.0nF  [C0402]
C626  1.0nF  [C0402]
C627  4.7nF  [C0402]
C628  0.01uF  [C0402]
C629  0.47uF  [C0603]
C630  0.1uF  [C0402]
C631  1uF  [C0402]
C632  1uF  [C0402]
C633  0.1uF  [C0402]
C634  0.47uF  [C0603]
C635  0.01uF  [C0402]
C636  4.7nF  [C0402]
C637  1.0nF  [C0402]
C638  1.0nF  [C0402]
C639  4.7nF  [C0402]
C640  0.01uF  [C0402]
C641  0.47uF  [C0603]
C642  0.1uF  [C0402]
C643  1uF  [C0402]
C644  1uF  [C0402]
C645  0.1uF  [C0402]
C646  0.47uF  [C0603]
C647  0.01uF  [C0402]
C648  4.7nF  [C0402]
C649  1.0nF  [C0402]
C650  1.0nF  [C0402]
C651  4.7nF  [C0402]
C652  0.01uF  [C0402]
C653  0.47uF  [C0603]
C654  0.1uF  [C0402]
C655  1uF  [C0402]
C656  12pF/DNP  [C0402]
C657  12pF/DNP  [C0402]
L37  120R, 100MHz,1.5A  [L0402]
L38  120R, 100MHz,1.5A  [L0402]
R431  22  [R0402]
R432  22  [R0402]
R433  22  [R0402]
R434  22  [R0402]
R435  22  [R0402]
R436  22  [R0402]
R437  22  [R0402]
R438  22  [R0402]
R439  22  [R0402]
R440  22  [R0402]
R441  49.9  [R0402]
R442  49.9  [R0402]
R443  49.9  [R0402]
R444  49.9  [R0402]
R445  49.9  [R0402]
R446  49.9  [R0402]
R447  49.9  [R0402]
R448  49.9  [R0402]
R449  49.9  [R0402]
R450  49.9  [R0402]
U55  SM802283  [QFN44-05P-7X7]
Y1  XTAL  [CX3225SB25000D0FPLCC]
sheet 39. CLOCK DISTRIBUTIONS-2
C658  10uF  [C0805]
C659  4.7uF  [C0805]
C660  0.47uF  [C0603]
C661  0.1uF  [C0402]
C662  0.047uF  [C0402]
C663  0.01uF  [C0402]
C664  4.7nF  [C0402]
C665  4.7nF  [C0402]
C666  0.01uF  [C0402]
C667  0.047uF  [C0402]
C668  0.1uF  [C0402]
C669  10uF  [C0805]
C670  1uF  [C0402]
C671  0.1uF  [C0402]
C672  0.47uF  [C0603]
C673  0.01uF  [C0402]
C674  4.7nF  [C0402]
C675  1.0nF  [C0402]
C676  1.0nF  [C0402]
C677  4.7nF  [C0402]
C678  0.01uF  [C0402]
C679  0.47uF  [C0603]
C680  0.1uF  [C0402]
C681  1uF  [C0402]
C682  1uF  [C0402]
C683  0.1uF  [C0402]
C684  0.47uF  [C0603]
C685  0.01uF  [C0402]
C686  4.7nF  [C0402]
C687  1.0nF  [C0402]
C688  1.0nF  [C0402]
C689  4.7nF  [C0402]
C690  0.01uF  [C0402]
C691  0.47uF  [C0603]
C692  0.1uF  [C0402]
C693  1uF  [C0402]
C694  1uF  [C0402]
C695  0.1uF  [C0402]
C696  0.47uF  [C0603]
C697  0.01uF  [C0402]
C698  4.7nF  [C0402]
C699  1.0nF  [C0402]
C700  1.0nF  [C0402]
C701  4.7nF  [C0402]
C702  0.01uF  [C0402]
C703  0.47uF  [C0603]
C704  0.1uF  [C0402]
C705  1uF  [C0402]
C706  12pF/DNP  [C0402]
C707  12pF/DNP  [C0402]
L39  120R, 100MHz,1.5A  [L0402]
L40  120R, 100MHz,1.5A  [L0402]
R451  22  [R0402]
R452  22  [R0402]
R453  22  [R0402]
R454  22  [R0402]
R455  22  [R0402]
R456  22  [R0402]
R457  22  [R0402]
R458  22  [R0402]
R459  22  [R0402]
R460  22  [R0402]
R461  49.9  [R0402]
R462  49.9  [R0402]
R463  49.9  [R0402]
R464  49.9  [R0402]
R465  49.9  [R0402]
R466  49.9  [R0402]
R467  49.9  [R0402]
R468  49.9  [R0402]
R469  49.9  [R0402]
R470  49.9  [R0402]
U56  SM802283  [QFN44-05P-7X7]
Y2  XTAL  [CX3225SB25000D0FPLCC]
sheet 40.TIVA ETHERNET
C708  0.1uF  [C0402]
C709  0.1uF  [C0402]
C710  0.1uF  [C0402]
C711  10NF  [C0402]
C712  1.0nF  [C0603]
C713  0.1uF  [C0402]
C714  0.1uF  [C0402]
C715  0.1uF  [C0402]
C716  0.1uF  [C0402]
C717  0.1uF  [C0402]
C718  0.1uF  [C0402]
C719  0.1uF  [C0402]
C720  0.1uF  [C0402]
L1M1  7490100161A  [XFMR_7490100161A]
R471  4.87K  [R0402]
R472  49.9  [R0402]
R473  49.9  [R0402]
R474  49.9  [R0402]
R475  49.9  [R0402]
R476  75  [R0603]
R477  75  [R0603]
R478  75  [R0603]
R479  75  [R0603]
T5  7490100161A  [XFMR_7490100161A]
sheet 42.TIVA POWER
U57  TM4C1294NCPDT-128-TQFP  [QFP40P1600X1600X120-128N]  (sections A,B,C)

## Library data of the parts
C559 C560 C562 C564-C566 C568 C572 C580 C581 = CAP_NONPOL: CAP CER 22UF 25V X5R 0805; Manufacturer: MURATA; Manufacturer Part Number: GRM21BR61E226ME44L; Tolerance: ±20%; Voltage: 25V
C561 C569 = CAP_NONPOL: CAP CER 0.22UF 25V 10% X7R 0603; Manufacturer: MURATA; Manufacturer Part Number: GRM188R71E224KA88D; Tolerance: ±10%; Voltage: 25V
C563 = CAP_NONPOL: CAP CER 220PF 50V NP0 0402; Manufacturer: KEMET; Manufacturer Part Number: C0402C221J5GACTU; Tolerance: ±10%; Voltage: 50V
C567 C582-C584 C587-C589 C593 C631 C643 C644 C655 C670 C681 C682 C693 C694 C705 = CAP_NONPOL: CAP-1.0UF,10%,10V,X5R,0402; Manufacturer: MURATA; Manufacturer Part Number: GRM155R61A105KE15D; Tolerance: ±10%; Voltage: 10V
L33 L36 = INDUCTOR_0: FIXED IND 1UH 5.2A 10 MOHM SMD; Manufacturer: WURTH; Manufacturer Part Number: 74404063010
L34 = INDUCTOR: FIXED IND 680NH 5.5A 19 MOHM SMD; Manufacturer: WURTH; Manufacturer Part Number: 744-3732-40068
R375 = RESISTOR_1: RES SMD 49.9K OHM 1% 1/16W 0402; Manufacturer: VISHAY DALE; Manufacturer Part Number: CRCW040249K9FKED; Tolerance: 1%; Wattage: 1/16W
R376 = RESISTOR_1: RES SMD 100K OHM 1% 1/16W 0402; Manufacturer: VISHAY DALE; Manufacturer Part Number: CRCW0402100KFKED; Tolerance: 1%; Wattage: 1/16W
R377 = RESISTOR_1: RES- 2.2 OHM 1/5W 1% 0402 SMD; Manufacturer: VISHAY DALE; Manufacturer Part Number: CRCW04022R20FKEDHP; Tolerance: ±1%; Wattage: 1/8W
R378 = RESISTOR_1: RES SMD 1M OHM 1% 1/16W 0402; Manufacturer: VISHAY DALE; Manufacturer Part Number: CRCW04021M00FKED; Tolerance: 1%; Wattage: 1/16W
R379 = RESISTOR_1: RES SMD 499 OHM 1% 1/16W 0402; Manufacturer: VISHAY DALE; Manufacturer Part Number: CRCW0402499RFKED; Tolerance: ±1%; Wattage: 1/16W
R380 R381 = RESISTOR_1: RES SMD 20K OHM 1% 1/16W 0402; Manufacturer: VISHAY DALE; Manufacturer Part Number: CRCW040220K0FKED; Tolerance: 1%; Wattage: 1/16W
R382 = RESISTOR_1: RES SMD 5.1 OHM 1% 1/4W 0603; Manufacturer: Panasonic; Manufacturer Part Number: ERJ-3BQF5R1V; Tolerance: ±1%; Wattage: 1/4W
R383 = RES: RES SMD 0.0 OHM JUMPER 1/8W 0805; Manufacturer: VISHAY DALE; Manufacturer Part Number: CRCW08050000Z0EA; Part Number: RC0805FR-070RL; WATTAGE: 1/16W
R872-R874 R879-R881 = R: RES SMD 0 OHM 1W 1812 WIDE; Manufacturer: Vishay Dale; Manufacturer Part Number: RCL12180000Z0EK
TP35-TP54 = T_POINT_R
U34 U41 = MP2131: Manufacturer: MPS; Manufacturer Part Number: MP2131GG
U35 = NB686: Manufacturer: MPS; Manufacturer Part Number: NB686GQ
C570 = CAP_NONPOL: CAP CER 2.2UF 10V X5R 0402; Manufacturer: TDK; Manufacturer Part Number: C1005X5R1A225K050BC; Tolerance: ±10%; Voltage: 10V
C571 C574 = CAP_NONPOL: CAP CER 10UF 16V X5R 0805; Manufacturer: MURATA; Manufacturer Part Number: GRM21BR61C106KE15K; Tolerance: ±10%; Voltage: 16V
C573 C575 C595-C597 C602 C605 C611 C618 C621 C630 C633 C642 C645 C654 C661 C668 C671 C680 C683 C692 C695 C704 = CAP_NONPOL: CAP CER 0.1UF 25V 10% X7R 0402; Manufacturer: MURATA; Manufacturer Part Number: GRM155R71C104KA88D; Tolerance: ±10%; Voltage: 25V
C576-C578 C913 = CAP_CER_0.1UF_10V_10%_X5R_0402: CAP CER 0.1UF 25V 10% X7R 0402; Alternate: C1005X7R1A104K050BB; Alternate Manufacturer: NA; Digikey: 445-7348-1-ND; MATERIAL: X7R; Manufacturer: TDK Corporation; PACK_TYPE: 0402P; PART_NUMBER: 0.1UF; Package: CAP_0402; Part Number: C1005X7R1E104K050BB; Section: KEYPAD; TOLERANCE: 10%; VOLTAGE: 25V
C579 = CAP_CER_0.1UF_10V_10%_X5R_0402: CAP CER 1000PF 100V X7R 0402; Alternate: C1005X7R1A104K050BB; Alternate Manufacturer: NA; Digikey: 490-6366-1-ND; MATERIAL: X7R; Manufacturer: Kemet; PACK_TYPE: 0402P; PART_NUMBER: 0.1UF; Package: CAP_0402; Part Number: GRM155R72A102KA01D; Section: KEYPAD; TOLERANCE: 10%; VOLTAGE: 100V
D17 = LED_wp117: LED GREEN CLEAR 0603 SMD; Manufacturer: Lite-On Inc; Part Number: LTST-C190KGKT; Section: 2G_MODULE
FB9 FB10 = FB_1: FERRITE CHIP 120 OHM 2000MA 0603; Alternate: NA; Alternate Manufacturer: NA; Digikey: 490-1037-1-ND; Manufacturer: Murata Electronics North America; Part Number: BLM18PG121SN1D
L35 = INDUCTOR_0: FIXED IND 2.2UH 3A 45 MOHM SMD; Manufacturer: Vishay; Manufacturer Part Number: IFSC1515AHER2R2M01
R384 = RESISTOR_1: RES SMD 200K OHM 1% 1/16W 0402; Manufacturer: VISHAY DALE; Manufacturer Part Number: CRCW0402200KFKED; Tolerance: ±1%; Wattage: 1/16W
R385 = RESISTOR_1: RES SMD 1.27K OHM 1% 1/10W 0402; Manufacturer: Panasonic; Manufacturer Part Number: ERJ-2RKF1271X; Part Number: 107B2110021D; Tolerance: 1%; Wattage: 1/10W
R386 = RESISTOR_1: RES SMD 133K OHM 1% 1/16W 0402; Manufacturer: VISHAY DALE; Manufacturer Part Number: CRCW0402133KFKED; Tolerance: ±1%; Wattage: 1/16W
R387 = RESISTOR_1: RES SMD 10K OHM 1% 1/16W 0402; Manufacturer: VISHAY DALE; Manufacturer Part Number: CRCW040210K0FKED; Part Number: CRCW040210K0FKED; Tolerance: 1%; Wattage: 1/16W
R388 R397 = RESISTOR_2: RES 10K OHM 1/10W 5% 0402 SMD; Alternate: NA; Alternate Manufacturer: NA; Digikey: P10KJCT-ND; Manufacturer: Panasonic Electronic Components; PACK_TYPE: 0402P; Part Number: ERJ-2GEJ103X; Section: 2G_MODULE; TOLERANCE: 5%; WATTAGE: 1/10W
R389 R393 = RES_1.0_OHM_1_16W_0402_SMD: RES SMD 10 OHM 1% 1/10W 0402; Alternate: MCS04020Z0000ZE000; Digikey: P10.0LCT-ND; MATERIAL: ?; Manufacturer: Panasonic Electronic Components; PACK_TYPE: 0402P; Part Number: ERJ-2RKF10R0X; Section: 2G_MODULE; TOLERANCE: 1%; Wattage: 1/10W
R390 = RES_0.9_OHM_1_10W_1%_0402_SMD: RES SMD 0.002 OHM 1% 2W 2512; Manufacturer: Stackpole Electronics Inc; PACK_TYPE: 2512P; Part Number: CSNL2512FT2L00; Section: ETH; TOLERANCE: 1%; WATTAGE: 2W
R391 = RES_0402
R392 = RESISTOR_2: RES SMD 620 OHM 5% 0.4W 0805; Alternate: NA; Alternate Manufacturer: NA; Digikey: RHM620KCT-ND; Manufacturer: Rohm Semiconductor; PACK_TYPE: 0805P; Part Number: ESR10EZPJ621; Section: 2G_MODULE; TOLERANCE: 1%; WATTAGE: 0.4W
R394 = RESISTOR_2: RES SMD 1M OHM 1% 1/16W 0402; Alternate: NA; Alternate Manufacturer: NA; Digikey: 311-1.00MLRCT-ND; Manufacturer: Yageo; PACK_TYPE: 0402P; Part Number: RC0402FR-071ML; Section: 2G_MODULE; TOLERANCE: 1%; WATTAGE: 1/16W
R395 = R_0: RES 150 OHM 1/10W 5% 0603 SMD; Manufacturer: Panasonic; Manufacturer Part Number: ERJ-3GEYJ151V; Package: SMT, 0603; Part Type: Thick Film; Power: 1/10W; Tolerance: 5%
R396 = RESISTOR_2: RES SMD 150K OHM 1% 1/16W 0402; Alternate: NA; Alternate Manufacturer: NA; Digikey: 311-150KLRCT-ND; Manufacturer: Yageo; PACK_TYPE: 0402P; Part Number: RC0402FR-07150KL; Section: 2G_MODULE; TOLERANCE: 1%; WATTAGE: 1/10W
R398 = RESISTOR_2: RES SMD 118K OHM 1% 1/16W 0402; Alternate: NA; Alternate Manufacturer: NA; Digikey: RMCF0402FT118KCT-ND; Manufacturer: Stackpole Electronics Inc; PACK_TYPE: 0402P; Part Number: RMCF0402FT118K; Section: 2G_MODULE; TOLERANCE: 1%; WATTAGE: 1/16w
R399 = RESISTOR_1: RES SMD 200K OHM 1% 1/16W 0402; Manufacturer: VISHAY DALE; Manufacturer Part Number: CRCW0402200KFKED; Tolerance: 1%; Wattage: 0.1W
R400 = RESISTOR_1: RES-61.9K,1%,1/16W,0402; Manufacturer: VISHAY DALE; Manufacturer Part Number: CRCW040261K9FKED; Tolerance: 1%; Wattage: 1/16W
U36 = MP2162: MP2162A, 2A, 6V, 1.5Mhz; Manufacturer: MPS
U37 = MP20051
U38 = INA226_6: IC MONITOR PWR/CURR BIDIR 10MSOP; Digikey: 296-29034-1-ND; Manufacturer: Texas Instruments; Part Number: INA226AIDGSR
U39 = TPS259241: IC EFUSE 12V BFET DVR 5A 10VSON; Digikey: TPS259241DRCR-ND; Manufacturer: Texas Instruments; Part Number: TPS259241DRCR
U40 = 74LVC1G08SE-7
C585 C599 C601 C604 C607 = CAP: CAP CER 470PF 50V X5R 0402; Assembly Option: LOAD; Manufacturer: TDK Corporation; Manufacturer PN: CGA2B2X5R1H471K050BA; Manufacturer Part Number: CGA2B2X5R1H471K050BA; PART_NUMBER: PAC_CAP_02528; Tolerance: 10%
C586 C591 C598 C600 C603 C606 = CAP: CAP  0402 CER 0.01uF 16V 10%  X7R; Assembly Option: LOAD; Manufacturer: Murata; Manufacturer PN: GRM155R71H103JA88D; Manufacturer Part Number: GRM155R71C103KA01J; PART_NUMBER: PAC_CAP_02518; Tolerance: 10%; Voltage: 16V
C590 C594 = cap_0402_2.2uF_25V_10%_X5R_smd: CAP CER 2.2UF 10V X5R 0402; Manufacturer: TDK; Manufacturer Part Number: C1005X5R1A225K050BC; Voltage: 10V
C592 = CAP: CAP CER 0.022UF 50V X5R 0402; Assembly Option: LOAD; Manufacturer: TDK Corporation; Manufacturer PN: CGA2B3X5R1H223K050BB; Manufacturer Part Number: CGA2B3X5R1H223K050BB; PART_NUMBER: PAC_CAP_02528; Tolerance: 10%; Voltage: 50V
D40-D43 = LED_wp117: LED GREEN DIFFUSED 0603 SMD; Manufacturer: Lumex; Manufacturer Part Number: SML-LX0603GW-TR; Part Number: LTST-C190KGKT
J17 J18 = 2_PIN_JUMPER: 2 Positions Header, Unshrouded, Breakaway Connector 0.100" (2.54mm) Through Hole Gold; Manufacturer: TE Connectivity; Manufacturer Part Number: 5-146280-2
Q13-Q16 = MOSFET_N_GDS: MOSFET N-CH 30V 300MA UMT3; Manufacturer: Rohm; Manufacturer Part Number: RJU003N03T106; PART_NUMBER: RJU003N03T106
R401 R403 R406 = RESISTOR_1: RES SMD 100K OHM 5% 1/16W 0402; Manufacturer: VISHAY DALE; Manufacturer Part Number: CRCW0402100KJNED; Tolerance: 5%; Wattage: 1/16W
R402 R417 R424 R427 R428 = RESISTOR_1: RES SMD 4.7K OHM 5% 1/16W 0402; Manufacturer: Panasonic; Manufacturer Part Number: ERJ-2GEJ472X; Tolerance: 5%; Wattage: 1/16W
R404 R407 R413 R414 R416 R423 = RESISTOR_1: RES SMD 10K OHM 5% 1/16W 0402; Manufacturer: VISHAY DALE; Manufacturer Part Number: CRCW040210K0JNED; Tolerance: ±5%; Wattage: 1/16W
R405 = RESISTOR_1: RES SMD 4.7K OHM 5% 1/16W 0402; Manufacturer: Panasonic; Manufacturer Part Number: ERJ-2GEJ472X; Tolerance: ±5%; Wattage: 1/16W
R408 = R_0: RES SMD 0.0OHM JUMPER 1/16W 0402; Manufacturer: VISHAY DALE; Manufacturer Part Number: CRCW04020000Z0ED; Power: 1/10W; Tolerance: 5%
R409 R410 = R_0: RES 150 OHM 1/10W 5% 0603 SMD; Manufacturer: VISHAY DALE; Manufacturer Part Number: CRCW04020000Z0ED; Power: 1/10W; Tolerance: 5%
R411 = RES_0402: RES SMD 10K OHM 5% 1/16W 0402
R892 R895 R897 R899 = R: RES 10 OHM 1/10W 1% 0402 SMD; MFG: Panasonic; MFG_PN: ERJ-2RKF10R0X; Manufacturer: Panasonic; Manufacturer Part Number: ERJ-2RKF10R0X; PART_NUMBER: ERJ-2RKF10R0X; Tolerance: 1%
R893 R894 R896 R898 = RESISTOR_1: RES SMD 200 OHM 1% 1/16W 0402; Manufacturer: VISHAY DALE; Manufacturer Part Number: CRCW0402200RFKED; Tolerance: 1%; Wattage: 1/16W
S1 = SWITCH_1: SWITCH TACTILE SPST-NO 0.05A 12V; Manufacturer: Omron Electronics Inc-EMC Div; Manufacturer Part Number: B3SL-1022P; Part Number: B3SL-1022P
U42 U44 U46 = 74LVC1G17: IC BUFFER SCHMITT TRIGGER 5TSSOP; Manufacturer: NXP; Manufacturer Part Number: 74LVC1G17GW,125
U43 U47 U51-U54 = IC_TPS3808G01DBVR: IC VOLT SUPERVISOR ADJ SOT23-6; Assembly Option: LOAD; Manufacturer: TI; PART_NUMBER: PAC_IC_00743
U45 U48 U50 = 74LVC1G07: IC BUFF OPEN DRAIN N-INV 5TSSOP; Manufacturer: NXP; Manufacturer Part Number: 74LVC1G07GW,125
U49 = 74LVC1G08SE-7: IC GATE AND 1CH 2-INP SOT-353; Manufacturer: Diodes
R412 R420 R425 R429 = RES_0: RES SMD 0.0OHM JUMPER 1/16W 0402; Assembly Option: LOAD; Manufacturer: VISHAY DALE; Manufacturer PN: ERJ-2RKF1002X; Manufacturer Part Number: CRCW04020000Z0ED; PART_NUMBER: PAC_RES_02050
R415 = RESISTOR_1: RES SMD 1K OHM 5% 1/16W 0402; Manufacturer: VISHAY DALE; Manufacturer Part Number: CRCW04021K00JNED; Tolerance: 5%; Wattage: 1/16W
R418 = RES_0: RES SMD 0.0OHM JUMPER 1/16W 0402; Assembly Option: DNL; Manufacturer: VISHAY DALE; Manufacturer PN: ERJ-2RKF1002X; Manufacturer Part Number: CRCW04020000Z0ED; PART_NUMBER: PAC_RES_02050
R419 = RES_0: RES SMD 10K OHM 5% 1/16W 0402; Assembly Option: LOAD; Manufacturer: VISHAY DALE; Manufacturer Part Number: CRCW040210K0JNED; Tolerance: ±5%
R421 = RES_0: RES SMD 1.74K OHM 1% 1/10W 0402; Assembly Option: LOAD; Manufacturer: Panasonic; Manufacturer PN: ERJ-2RKF4990X; Manufacturer Part Number: ERJ-2RKF1741X; PART_NUMBER: PAC_RES_02713; Tolerance: 1%
R422 R426 R430 = RES_0: RES SMD 499 OHM 1% 1/16W 0402; Assembly Option: LOAD; Manufacturer: VISHAY DALE; Manufacturer PN: ERJ-2RKF4990X; Manufacturer Part Number: CRCW0402499RFKED; PART_NUMBER: PAC_RES_02713; Tolerance: 1%
TP55-TP63 = TEST_POINT
C608 C619 C658 C669 = cap_0805_10uF_16V_10%_X5R
C609 C659 = cap_0805_4.7uF_10V_10%_X5R
C610 C696 = CAP_NONPOL: CAP CER 0.47UF 16V X5R 0402; Manufacturer: MURATA; Manufacturer Part Number: GRM155R71C104KA88D; Tolerance: ±10%; Voltage: 16V
C612 C617 C662 C667 = CAP_NONPOL: CAP CER 0.047UF 25V X7R 0402; Manufacturer: MURATA; Manufacturer Part Number: GRM155R71E473KA88J; Tolerance: ±10%; Voltage: 25V
C613 C616 C623 C628 C635 C640 C647 C652 C663 C666 C673 C678 C685 C690 C697 C702 = cap_0402_0.01uF_16V_10%_X7R: CAP  0402 CER 0.01uF 16V 10%  X7R; Manufacturer: Murata; Manufacturer Part Number: GRM155R71C103KA01J; Voltage: 16V
C614 C615 C624 C627 C636 C639 C648 C651 C664 C665 C677 C686 C689 C698 C701 = CAP_NONPOL: CAP CER 4.7nF 50V X7R 0402; Manufacturer: MURATA; Manufacturer Part Number: GRM155R71C104KA88D; Tolerance: ±10%; Voltage: 50V
C620 = CAP_NONPOL: CAP CER 1UF 10V 10% X7S 0402; MFG: Murata; MFG_PN: GCM155C71A105KE38D; Manufacturer: TDK; Manufacturer Part Number: C1005X7S1A105K050BC; Tolerance: ±10%; Voltage: 10V
C622 C629 C634 C641 C646 C653 C660 C672 C679 C684 C691 C703 = CAP_NONPOL: CAP CER 0.47UF 16V X5R 0603; Manufacturer: MURATA; Manufacturer Part Number: GRM188R71C474KA88D; Tolerance: ±10%; Voltage: 16V
C625 C626 C637 C638 C649 C650 C675 C676 C687 C688 C699 C700 = CAP_NONPOL: CAP CER 1.0nF 50V X7R 0402; Manufacturer: KEMET; Manufacturer Part Number: C0402T102K5RACTU; Tolerance: ±10%; Voltage: 50V
C632 = CAP_NONPOL: CAP-1.0UF,10%,10V,X7S,0402; Manufacturer: MURATA; Manufacturer Part Number: GRM155R61A105KE15D; Tolerance: ±10%; Voltage: 10V
C656 C657 C706 C707 = CAP_CER_0.1UF_10V_10%_X5R_0402: CAP CER 12PF 50V NP0 0402; MATERIAL: NPO; Manufacturer: Kemet; Manufacturer Part Number: CBR04C120F5GAC; PART_NUMBER: 0.1UF; Part Number: CBR04C120F5GAC; TOLERANCE: 1%; VOLTAGE: 50V
L37-L40 = FERRITE_BEAD_0: FILTER CHIP 120 OHM 1.5A 0402; Manufacturer: MURATA; Manufacturer Part Number: BLM15EG121SN1D
R431-R440 R451-R460 = RESISTOR_1: RES SMD 22 OHM 1% 1/16W 0402; Manufacturer: VISHAY DALE; Manufacturer Part Number: CRCW040222R0FKED; Tolerance: ±1%; Wattage: 1/16W
R441-R450 R461-R470 R472-R475 = RESISTOR_1: RES SMD 49.9 OHM 1% 1/10W 0402; Manufacturer: Panasonic; Manufacturer Part Number: ERJ-2RKF49R9X; Tolerance: 1%; Wattage: 1/16W
U55 U56 = SM802283: Manufacturer: Microchip
Y1 Y2 = XTAL_4pin: 25MHz  Crystal 8pF 50 Ohm -40- 85 Surface Mount 4-SMD, No Lead; Manufacturer: AVX Corp/Kyocera Corp
C674 = CAP_NONPOL: CAP CER 4.7nF 50V X7R 0402; Manufacturer: MURATA; Manufacturer Part Number: GCM155R71H472KA37D; Tolerance: ±10%; Voltage: 50V
C708-C710 C713 C714 = CAP_CER_0.1UF_10V_10%_X5R_0402: CAP CER 0.1UF 25V 10% X7R 0402; MATERIAL: X7R; Manufacturer: MURATA; Manufacturer Part Number: GRM155R71C104KA88D; PART_NUMBER: 0.1UF; Part Number: C1005X7R1E104K050BB; TOLERANCE: 10%; VOLTAGE: 25V
C711 = CAP_CER_0.1UF_10V_10%_X5R_0402: CAP CER 10000PF 16V 10% X7R 0402; MATERIAL: X7R; Manufacturer: Yageo; PART_NUMBER: 0.1UF; Part Number: CC0402KRX7R7BB103; TOLERANCE: 10%; VOLTAGE: 16V
C712 = CAP_CER_0.1UF_10V_10%_X5R_0402: CAP CER 1000PF 50V 5% NP0 0603; MATERIAL: NP0; Manufacturer: TDK Corporation; PART_NUMBER: 0.1UF; Part Number: C1608C0G1H102J080AA; TOLERANCE: 5%; VOLTAGE: 50V
C715 C716 = cap_0402_0.1uF_16V_10%_X7R: CAP CER 0.1UF 25V 10% X7R 0402; MATERIAL: X7R; MFG: TAIYO; MFG_PN: TMK105BJ104KV-F; Manufacturer: MURATA; Manufacturer Part Number: GRM155R71C104KA88D; PART_NUMBER: G41157-001; PATH: I14; PHYS_PAGE: 39; Part Number: C1005X7R1E104K050BB; TOLERANCE: 10%; VOLTAGE: 25V; XY: -6,252,200
C717-C720 = cap_0402_0.1uF_16V_10%_X7R: CAP CER 0.1UF 25V 10% X7R 0402; MATERIAL: X7R; MFG: TAIYO; MFG_PN: TMK105BJ104KV-F; Manufacturer: MURATA; Manufacturer Part Number: GRM155R71C104KA88D; PART_NUMBER: G41157-001; PATH: I13; PHYS_PAGE: 39; Part Number: C1005X7R1E104K050BB; TOLERANCE: 10%; VOLTAGE: 25V; XY: -6,252,000
L1M1 T5 = TRANS-DA2125_3: TRANSFORMER 10/100 BASE-T SMD; MATERIAL: #N/A; Manufacturer: Wurth Electronics Midcom; TOLERANCE: #N/A; VOLTAGE: #N/A; WATTAGE: #N/A
R471 = RESISTOR_1: RES SMD 4.87K OHM 1% 1/16W 0402; Manufacturer: Stackpole Electronics Inc.; Manufacturer Part Number: RMCF0402FT4K87; Part Number: RMCF0402FT4K87; Tolerance: 1%; Wattage: 1/16W
R476-R479 = RES_0: RES SMD 75 OHM 1% 1/8W 0603; Assembly Option: LOAD; Manufacturer: Stackpole Electronics Inc.; Manufacturer PN: RNCP0603FTD75R0; Manufacturer Part Number: RNCP0603FTD75R0; PART_NUMBER: PAC_RES_01894; Tolerance: 1%
U57 = TM4C1294NCPDT-128-TQFP_12: IC MCU 32BIT 1024KB FLASH 128TQF; Manufacturer: Texas Instruments; Manufacturer Part Number: TM4C1294NCPDTT3; Part Number: TM4C1294NCPDTT3

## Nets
12V_VIN_TRXFE_CM: C577.1(A[0]) FB9.2 FB10.2 R390.2(B[0]) R393.2(B[0]) R394.2 U38.8(VBUS) U39.3(VIN) U39.4(VIN1) U39.5(VIN2)
GND: C559.2 C560.2 C562.2 C564.2 C565.2 C566.2 C567.2 C568.2 C569.2 C570.2 C571.2 C572.2 C573.2 C574.2 C575.2 C576.1(A[0]) C577.2(B[0]) C579.2(B[0]) C580.2 C581.2 C582.2 C583.2 C584.2 C585.2 C586.1 C587.2 C588.2 C589.2 C590.2 C591.1 C592.2 C593.2 C594.2 C595.2 C596.2 C597.2 C598.1 C599.2 C600.1 C601.2 C602.2 C603.1 C604.2 C605.2 C606.1 C607.2 C608.1 C609.1 C610.2 C611.2 C612.2 C613.1 C614.2 C615.2 C616.1 C617.2 C618.2 C619.1 C620.2 C621.2 C622.2 C623.1 C624.2 C625.2 C626.2 C627.2 C628.1 C629.2 C630.2 C631.2 C632.2 C633.2 C634.2 C635.1 C636.2 C637.2 C638.2 C639.2 C640.1 C641.2 C642.2 C643.2 C644.2 C645.2 C646.2 C647.1 C648.2 C649.2 C650.2 C651.2 C652.1 C653.2 C654.2 C655.2 C656.1(A[0]) C657.2(B[0]) C658.1 C659.1 C660.2 C661.2 C662.2 C663.1 C664.2 C665.2 C666.1 C667.2 C668.2 C669.1 C670.2 C671.2 C672.2 C673.1 C674.2 C675.2 C676.2 C677.2 C678.1 C679.2 C680.2 C681.2 C682.2 C683.2 C684.2 C685.1 C686.2 C687.2 C688.2 C689.2 C690.1 C691.2 C692.2 C693.2 C694.2 C695.2 C696.2 C697.1 C698.2 C699.2 C700.2 C701.2 C702.1 C703.2 C704.2 C705.2 C706.1(A[0]) C707.2(B[0]) C708.2(B[0]) C709.2(B[0]) C710.2(B[0]) C711.2(B[0]) C712.2(B[0]) C713.2(B[0]) C714.2(B[0]) C715.2 C716.2 C717.2 C718.2 C719.1 C720.1 C913.2(B[0]) D17.K J17.2 J18.2 Q13.S Q14.S Q15.S Q16.S R376.1 R381.1 R383.2(Pin2) R386.1 R387.1 R396.1 R397.2 R398.1 R400.1 R401.1 R403.1 R406.1 R421.2 R422.2 R426.2 R430.2 R441.1 R442.1 R443.1 R444.1 R445.1 R446.1 R447.1 R448.1 R449.1 R450.1 R461.1 R462.1 R463.1 R464.1 R465.1 R466.1 R467.1 R468.1 R469.1 R470.1 R471.1 S1.1 S1.2 TP36.1(TP) TP38.1(TP) TP40.1(TP) TP43.1(TP) TP44.1(TP) TP46.1(TP) TP47.1(TP) TP48.1(TP) TP49.1(TP) TP50.1(TP) TP51.1(TP) U34.3(PGND1) U34.4(AGND) U34.12(PGND2) U35.2(PGND) U35.4(AGND) U36.3(AGND) U36.5(PGND) U37.4(GND) U37.9(EPAD) U38.7(GND) U39.11(PAD) U40.3(GND) U41.3(PGND1) U41.4(AGND) U41.12(PGND2) U42.3(GND) U43.2(GND) U44.3(GND) U45.3(GND) U46.3(GND) U47.2(GND) U48.3(GND) U49.3(GND) U50.3(GND) U51.2(GND) U52.2(GND) U53.2(GND) U54.2(GND) U55.3(VSS02_2) U55.6(VSS02_3) U55.21(VSS1) U55.23(VSS2) U55.24(VSS01_1) U55.39(VSS01_2) U55.40(VSS02_1) U55.45(EP) U56.3(VSS02_2) U56.6(VSS02_3) U56.21(VSS1) U56.23(VSS2) U56.24(VSS01_1) U56.39(VSS01_2) U56.40(VSS02_1) U56.45(EP) U57.55(GND) U57.58(GND1) Y1.2 Y1.4 Y2.2 Y2.4 ; also on sheet 1 2 10 11 12 13 14 15 16 17 18 19 20 21 22 23 24 25 26 27 28 29 37 38 39 40 41 42 43 44 45 46 47 48 49 50 51 52 53 54
V0P9: R872.2 TP35.1(TP) ; also on sheet 14
V0P9_DLM: C560.1 L33.2 R375.2 R872.1 U34.6(OUT)
V0P9_PLL: R880.2 TP42.1(TP) ; also on sheet 51
V0P9_PLL_DC: C574.1 C575.1 R385.2 R880.1 U37.1(OUT1) U37.2(OUT2)
V1P2_DDR: R873.2 TP37.1(TP) ; also on sheet 11 12 13 16
V1P2_DDR_R: C563.1 C564.1 C565.1 C566.1 L34.2 R380.2 R873.1 U35.6(VDDQ)
V1P5: R881.2 TP41.1(TP) ; also on sheet 14 26 27 51
V1P5_DC: C572.1 L35.2 R384.2 R881.1 U36.4(OUT)
V2P5: R879.2 TP45.1(TP) ; also on sheet 11 50 51 53
V2P5_DC: C581.1 L36.2 R399.2 R879.1 U41.6(OUT)
V3P3: C570.1 C571.1 C573.1 C582.1 C583.1 C584.1 C586.2 C587.1 C588.1 C589.1 C591.2 C593.1 C595.1 C596.1 C597.1 C602.1 C605.1 C608.2 C619.2 C620.1 C621.1 C622.1 C623.2 C624.1 C625.1 C626.1 C627.1 C628.2 C629.1 C630.1 C631.1 C632.1 C633.1 C634.1 C635.2 C636.1 C637.1 C638.1 C639.1 C640.2 C641.1 C642.1 C643.1 C644.1 C645.1 C646.1 C647.2 C648.1 C649.1 C650.1 C651.1 C652.2 C653.1 C654.1 C655.1 C658.2 C669.2 C670.1 C671.1 C672.1 C673.2 C674.1 C675.1 C676.1 C677.1 C678.2 C679.1 C680.1 C681.1 C682.1 C683.1 C684.1 C685.2 C686.1 C687.1 C688.1 C689.1 C690.2 C691.1 C692.1 C693.1 C694.1 C695.1 C696.1 C697.2 C698.1 C699.1 C700.1 C701.1 C702.2 C703.1 C704.1 C705.1 L37.1 L38.1 L39.1 L40.1 R382.2 R402.2 R404.2 R405.2 R407.2 R411.2 R413.2 R414.2 R415.2 R416.2 R417.2 R420.1 R423.2 R424.2 R425.1 R427.2 R428.2 R429.1 R893.2 R894.2 R896.2 R898.2 U36.7(VIN) U37.7(VIN1) U37.8(VIN2) U42.5(VCC) U43.5(SENSE) U43.6(VDD) U44.5(VCC) U45.5(VCC) U46.5(VCC) U47.5(SENSE) U47.6(VDD) U48.5(VCC) U49.5(VCC) U50.5(VCC) U51.6(VDD) U52.6(VDD) U53.6(VDD) U54.6(VDD) U55.16(VDD02_2) U55.31(VDD01_1) U55.37(VDD01_2) U55.38(VDD01_3) U55.43(VDD02_1) U55.44(VDD02_3) U56.16(VDD02_2) U56.31(VDD01_1) U56.37(VDD01_2) U56.38(VDD01_3) U56.43(VDD02_1) U56.44(VDD02_3) ; also on sheet 10 11 12 14 17 18 22 24 25 26 27 29 43 45 49 51 53 54
V3P3_PG: R418.1 TP58.1 ; also on sheet 52
V3P3_TIVA_FIL: C708.1(A[0]) C709.1(A[0]) C710.1(A[0]) C711.1(A[0]) C712.1(A[0]) C713.1(A[0]) C714.1(A[0]) C716.1 C718.1 R472.2 R473.2 R474.2 R475.2 T5.10(TX_B) T5.15(TX_A) U57.51(VDD1) U57.52(VDD) ; also on sheet 38
V3P3_TIVA_LT: C576.2(B[0]) C913.1(A[0]) R388.2 R391.1 U38.6(VS) U40.5(VCC) ; also on sheet 1 2 19 20 21 28 29 37 38 39 40 42 43 44 46 47 52 54
V5P0: C559.1 C580.1 R419.1 U34.1(PVIN) U34.10(VIN) U41.1(PVIN) U41.10(VIN) ; also on sheet 18 25 29 38 49
V5P0_PG: R412.1 TP55.1 ; also on sheet 29
V12P0: R389.2(B[0]) R390.1(A[0]) ; also on sheet 18 21 28
V12P0_OCT_R: C562.1 U35.1(VIN) ; also on sheet 28 29 54
A_TRXFE_12V_ONOFF: R394.1 R396.2 U39.2(EN/UVLO) U40.4(Y)
DDR_100M_REFCLK_N: R452.2 R462.2 ; also on sheet 12
DDR_100M_REFCLK_P: R451.2 R461.2 ; also on sheet 12
DLM0_REF_CLK_100MHZ_N: R434.2 R444.2 ; also on sheet 50
DLM0_REF_CLK_100MHZ_P: R433.2 R443.2 ; also on sheet 50
DLM1_REF_CLK_100MHZ_N: R436.2 R446.2 ; also on sheet 50
DLM1_REF_CLK_100MHZ_P: R435.2 R445.2 ; also on sheet 50
DLM2_REF_CLK_100MHZ_N: R438.2 R448.2 ; also on sheet 50
DLM2_REF_CLK_100MHZ_P: R437.2 R447.2 ; also on sheet 50
DLM3_REF_CLK_100MHZ_N: R440.2 R450.2 ; also on sheet 50
DLM3_REF_CLK_100MHZ_P: R439.2 R449.2 ; also on sheet 50
DLMC_REF_CLK1_N: R432.2 R442.2 ; also on sheet 12
DLMC_REF_CLK1_P: R431.2 R441.2 ; also on sheet 12
ENABLE_STAGE2: R415.1 R895.1 TP56.1 U34.8(EN) U36.1(EN) U37.5(EN) U41.8(EN) U50.4(Y)
ENABLE_STAGE3: R424.1 R897.1 TP61.1 U53.1(~{RST}) ; also on sheet 52
ENABLE_STAGE4: R428.1 R899.1 TP62.1 U35.15(EN2) U35.16(EN1) U54.1(~{RST})
ENABLE_STAGE5: R417.1 TP57.1 U42.2(A) U43.3(~{MR}) U51.1(~{RST}) ; also on sheet 10
ETHSW_TIVA_P0_TXN: L1M1.14(X-_A) ; also on sheet 19
ETHSW_TIVA_P0_TXP: L1M1.16(X+_A) ; also on sheet 19
GPIO37_MEM_RST_L: R407.1 TP54.1(TP) U48.2(A) ; also on sheet 10
MANUAL_MEM_RST_L: C594.1 J18.1 R404.1 U46.2(A) U47.1(~{RST}) U48.4(Y)
MANUAL_RST_L: C590.1 R405.1 R408.2 S1.3 S1.4 ; also on sheet 12
MEM_RESET_L: R406.2 TP53.1(TP) U46.4(Y) ; also on sheet 22 43 44 45 49
MINI_PCIE0_100MHZ_N: R456.2 R464.2 ; also on sheet 26
MINI_PCIE0_100MHZ_P: R455.2 R463.2 ; also on sheet 26
MINI_PCIE1_100MHZ_N: R458.2 R466.2 ; also on sheet 27
MINI_PCIE1_100MHZ_P: R457.2 R465.2 ; also on sheet 27
OCT_DC_OK: R401.2 R892.1 U42.4(Y) ; also on sheet 12 37
OCT_RESET_L: R403.2 TP52.1(TP) U44.4(Y) ; also on sheet 12
OCT_USB_REF_CLK_N: R454.2 R470.2 ; also on sheet 53
OCT_USB_REF_CLK_P: R453.2 R469.2 ; also on sheet 53
PCIE0_GBC_CLKN: R460.2 R468.2 ; also on sheet 42
PCIE0_GBC_CLKP: R459.2 R467.2 ; also on sheet 42
PG_STAGE2: R423.1 TP60.1 U34.9(PG) U36.8(PG) U41.9(PG) U53.3(~{MR})
PG_STAGE3: R427.1 TP63.1 U54.3(~{MR}) ; also on sheet 52
PG_STAGE4: R416.1 TP59.1 U35.12(PG) U51.3(~{MR})
SCHMTT_SYS_RST_L: R402.1 U43.1(~{RST}) U44.2(A) U45.4(Y) U47.3(~{MR})
T_ETHSW_TIVA_P0_TXN: R473.1 T5.14(X-_A) U57.53(EN0RXIN)
T_ETHSW_TIVA_P0_TXP: R472.1 T5.16(X+_A) U57.54(EN0RXIP)
T_RXN: L1M1.8(D-_B) T5.8(D-_B)
T_RXP: L1M1.6(D+_B) T5.6(D+_B)
T_TIVA_ETHSW_P0_RXN: R475.1 T5.9(X-_B) U57.56(EN0TXON)
T_TIVA_ETHSW_P0_RXP: R474.1 T5.11(X+_B) U57.57(EN0TXOP)
T_TXN: L1M1.3(D-_A) T5.3(D-_A)
T_TXP: L1M1.1(D+_A) T5.1(D+_A)
THERM_ALERT: R395.2 ; also on sheet 42
TIVA_ETHSW_P0_RXN: L1M1.9(X-_B) ; also on sheet 19
TIVA_ETHSW_P0_RXP: L1M1.11(X+_B) ; also on sheet 19
TIVA_OCT_RESETn: R410.2 ; also on sheet 40
TIVA_PWRMNTR_I2C6_SCLK: U38.5(SCL) ; also on sheet 1 28 29 37 38 43
TIVA_PWRMNTR_I2C6_SDA: U38.2(A0) U38.4(SDA) ; also on sheet 1 28 29 37 38 43
TRXFE_12V_ONOFF: U40.2(B) ; also on sheet 37 47
TRXFE_IN_12V: FB9.1 FB10.1 R392.2 U39.6(OUT) U39.7(OUT1) U39.8(OUT2) ; also on sheet 42
TRXFE_PWR_ALRT: R388.1 U38.3(ALERT) ; also on sheet 1
VREF_DDR: C569.1 U35.7(VTTREF) ; also on sheet 11
VTT_DDR: R874.2 TP39.1(TP) ; also on sheet 11
VTT_DDR_R: C568.1 R874.1 U35.5(VTT) U35.8(VTTS)
N309349: C715.1 L1M1.15(TX_A)
N309387: C717.1 L1M1.10(TX_B)
N309461: L1M1.7(TD_B) R478.2
N309495: C719.2 R477.1 R478.1
N309685: C720.2 R476.2 R479.2
N310451: R471.2 U57.59(RBIAS)
N21892189: J17.1 R409.1 U45.2(A)
N23982717: C567.1 R382.1 U35.3(3V3)
N23982781: R383.1(Pin1) U35.14(MODE)
N23982814: C561.2 L34.1 R378.2 U35.9(SW)
N23982816: R377.2 U35.10(BST)
N23982829: C561.1 R377.1
N23982910: C563.2 R378.1 R379.2
N23982912: R379.1 R380.1 R381.2 U35.13(FB)
N23984587: L33.1 U34.2(SW1) U34.11(SW2)
N23984616: R375.1 R376.2 U34.7(FB)
N23989157: L36.1 U41.2(SW1) U41.11(SW2)
N23989177: R399.1 R400.2 U41.7(FB)
N24725622: C585.1 U43.4(CT)
N24728007: C592.1 U47.4(CT)
N24733182: R385.1 R387.2 U37.3(FB)
N24735338: R414.1 U50.2(A) U52.1(~{RST})
N24735404: C599.1 U52.4(CT)
N24735440: R412.2 R413.1 R418.2 U52.3(~{MR})
N24735486: C598.2 R419.2 R421.1 U52.5(SENSE)
N24736210: C601.1 U51.4(CT)
N24736294: C600.2 R420.2 R422.1 U51.5(SENSE)
N24736645: C604.1 U53.4(CT)
N24736725: C603.2 R425.2 R426.1 U53.5(SENSE)
N24737097: C607.1 U54.4(CT)
N24737181: C606.2 R429.2 R430.1 U54.5(SENSE)
N30157604: R384.1 R386.2 U36.2(FB)
N30157670: L35.1 U36.6(SW)
N30868620: C656.2(B[0]) U55.18(XIN) Y1.3
N30868622: C657.1(A[0]) U55.19(XOUT) Y1.1
N30870342: R431.1 U55.26(QA)
N30870345: R432.1 U55.25(QAN)
N31216781: R476.1 T5.2(TD_A)
N31216805: R479.1 T5.7(TD_B)
N31561328: C609.2 C610.1 C611.1 C612.1 C613.2 C614.1 L37.2 U55.10(VDD1) U55.13(VDD2)
N31568335: C615.1 C616.2 C617.1 C618.1 L38.2 U55.12(VDDA)
N31579907: R433.1 U55.42(QE)
N31579909: R434.1 U55.41(QEN)
N31579973: R435.1 U55.2(QF)
N31579975: R436.1 U55.1(QFN)
N31580127: R437.1 U55.5(QG)
N31580129: R438.1 U55.4(QGN)
N31580219: C706.2(B[0]) U56.18(XIN) Y2.3
N31580220: C707.1(A[0]) U56.19(XOUT) Y2.1
N31580231: R451.1 U56.5(QG)
N31580232: R452.1 U56.4(QGN)
N31580299: C659.2 C660.1 C661.1 C662.1 C663.2 C664.1 L39.2 U56.10(VDD1) U56.13(VDD2)
N31580371: C665.1 C666.2 C667.1 C668.1 L40.2 U56.12(VDDA)
N31580406: R453.1 U56.29(QB)
N31580407: R454.1 U56.28(QBN)
N31580410: R455.1 U56.42(QE)
N31580411: R456.1 U56.41(QEN)
N31580414: R457.1 U56.2(QF)
N31580415: R458.1 U56.1(QFN)
N31586955: R460.1 U56.7(QHN)
N31586957: R459.1 U56.8(QH)
N31590201: R439.1 U55.8(QH)
N31590213: R440.1 U55.7(QHN)
N31592618: R410.1 R411.1 U49.2(B)
N31592622: R408.1 U49.1(A)
N31593345: R409.2 U49.4(Y)
N32342637: L1M1.2(TD_A) R477.2
N33532546: D40.K Q13.D
N33532651: Q13.G R892.2
N33532902: D41.K Q14.D
N33532932: Q14.G R895.2
N33533090: D42.K Q15.D
N33533120: Q15.G R897.2
N33533333: D43.K Q16.D
N33533363: Q16.G R899.2
N33593042: R391.2 R395.1 U40.1(A)
N33593075: D17.A R392.1
N33593148: R398.2 U39.10(ILIM)
N33593156: C579.1(A[0]) U39.1(DV/DT)
N33593430: C578.1(A[0]) R389.1(A[0]) U38.10(IN+)
N33593432: C578.2(B[0]) R393.1(A[0]) U38.9(IN-)
N33593473: R397.1 U38.1(A1)
N34191262: D41.A R894.1
N34191263: D43.A R898.1
N34191264: D42.A R896.1
N34191462: D40.A R893.1

Not connected (* = marked no-connect by the designer): L1M1 4* 5* 12* 13*; T5 4* 5* 12* 13*; U34 5(NC)*; U35 11(OTW)*; U37 6(NC)*; U39 9(BFET)*; U41 5(NC)*; U42 1(NC)*; U44 1(NC)*; U45 1(NC)*; U46 1(NC)*; U48 1(NC)*; U50 1(NC)*; U55 9(DNC1)* 11(DNC2)* 14(DNC9) 15(DNC10) 17(DNC7)* 20(DNC3)* 22(DNC8)* 27(DNC5)* 28(QBN) 29(QB) 30(DNC4)* 32(QCN) 33(QC) 34(DNC6)* 35(QDN) 36(QD); U56 9(DNC1)* 11(DNC2)* 14(DNC9) 15(DNC10) 17(DNC7)* 20(DNC3)* 22(DNC8)* 25(QAN) 26(QA) 27(DNC5)* 30(DNC4)* 32(QCN) 33(QC) 34(DNC6)* 35(QDN) 36(QD)

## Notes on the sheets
sheet 30
- 0p9_dlm
- use large copper shape
- R1218 JUMPER
- use large copper shape
- R1218 JUMPER
- at least 100mil width
- R1218 JUMPER
- use large copper shape
sheet 31
- (2A)
- R1218 JUMPER
- vout=0.8*(1+R1/R2)
- voperation 4.5~13.8
- A0: SDA
  A1:GND
- 12V TRXFE POWER MONITOR
- Adress:0X42
- R1218 JUMPER
- GND TEST POINTS
sheet 32
- POWERUP SEQUENCE
- all dc is okay
- (3msec)
- MANUAL SYSTEM RESET
- (127msec)
- RESET TO EMMC/mSATA/PHY
- MANUAL IF RESET
sheet 33
- Tdelay=3.2ms
- stage 1 is okay
- Delay=Ct(pF)/175+0.5ms
- stage 2 is okay
- Td=ct(pf)/175+0.5(ms)
- stage3 is okay
sheet 34
- GRM155R71E103KA01D 0.01uF
- CL05B472JB5NNNC  4.7NF
- GCM155R71H102KA37D  1.0nF
- GRM155R71E473KA88D  0.047uF
- 100 MHz Clk out HCSL to DLM1
- 100 MHz Clk out
- CLOCK 100MHz
sheet 35
- 100 MHz Clk out HCSL to DDR
- TO USB
- to mPCIE connector0
- to mPCIE connector1
- TO SDR CONNECTOR
- CLOCK 100MHz
sheet 36
- 8
- 7
- 6
- 5
- 4
- 3
- 2
- 1
- D
- D
- C
- C
- B
- B
- from SWITCH
- A
- A
- 8
- 7
- 6
- 5
- 4
- 3
- 2
- 1
